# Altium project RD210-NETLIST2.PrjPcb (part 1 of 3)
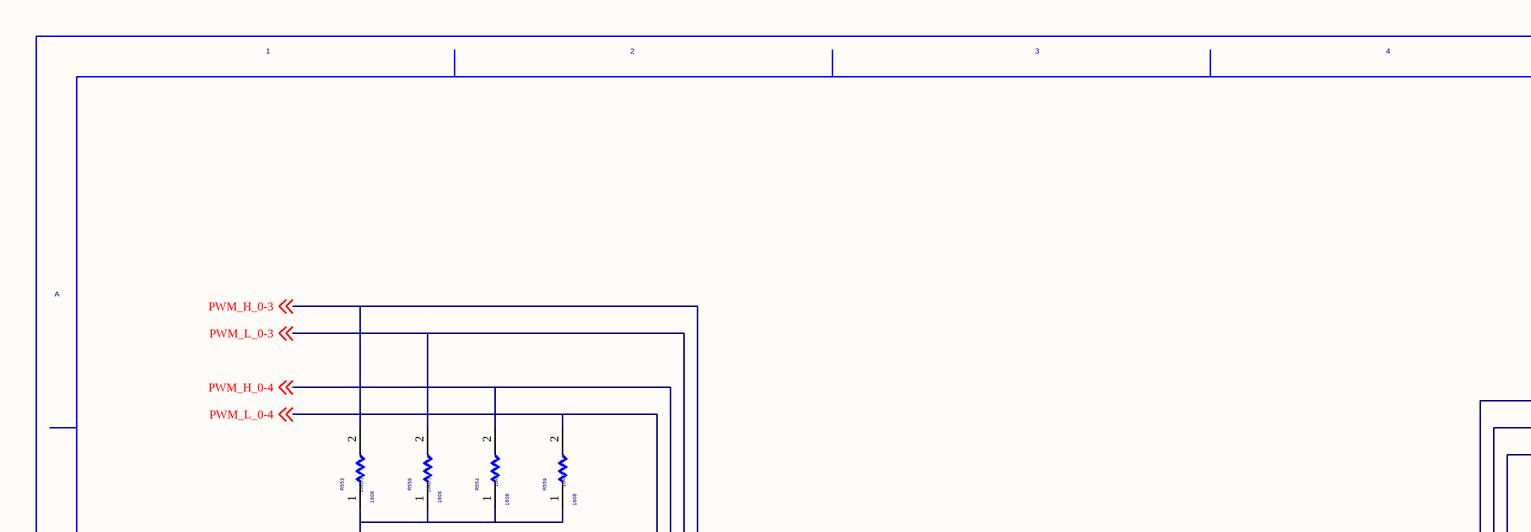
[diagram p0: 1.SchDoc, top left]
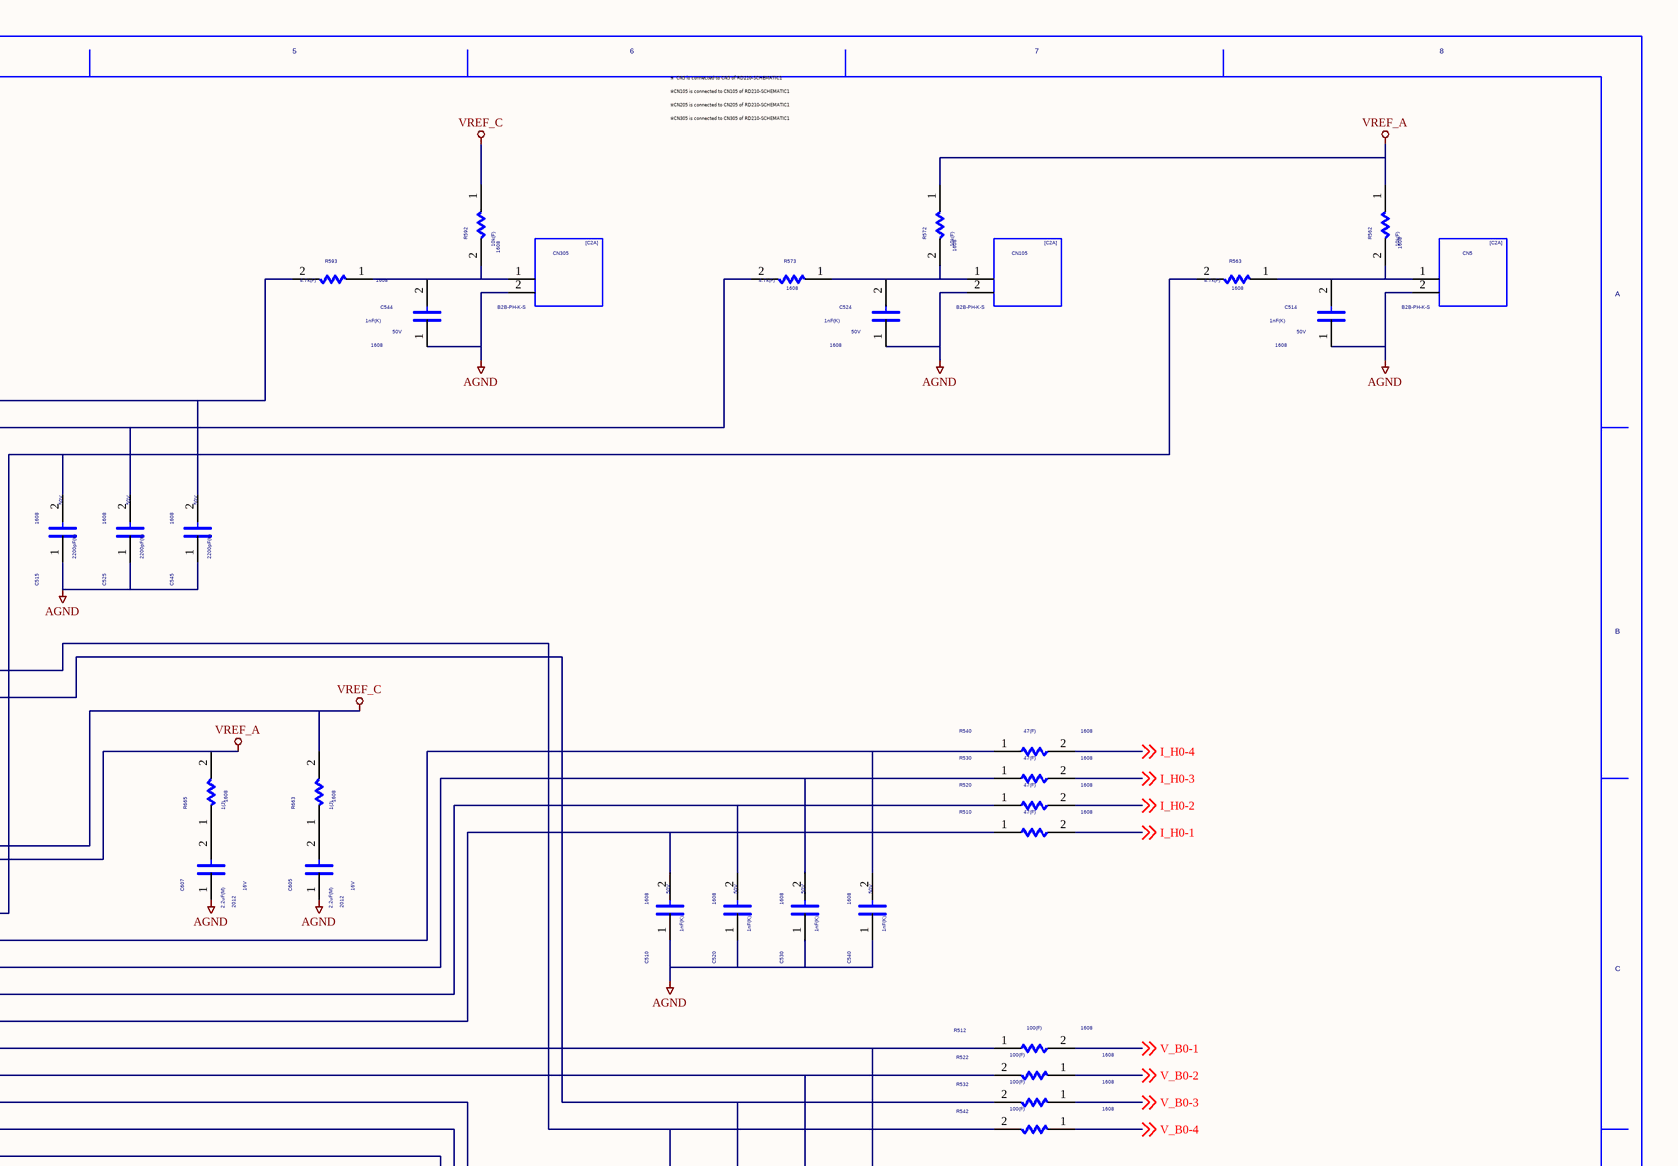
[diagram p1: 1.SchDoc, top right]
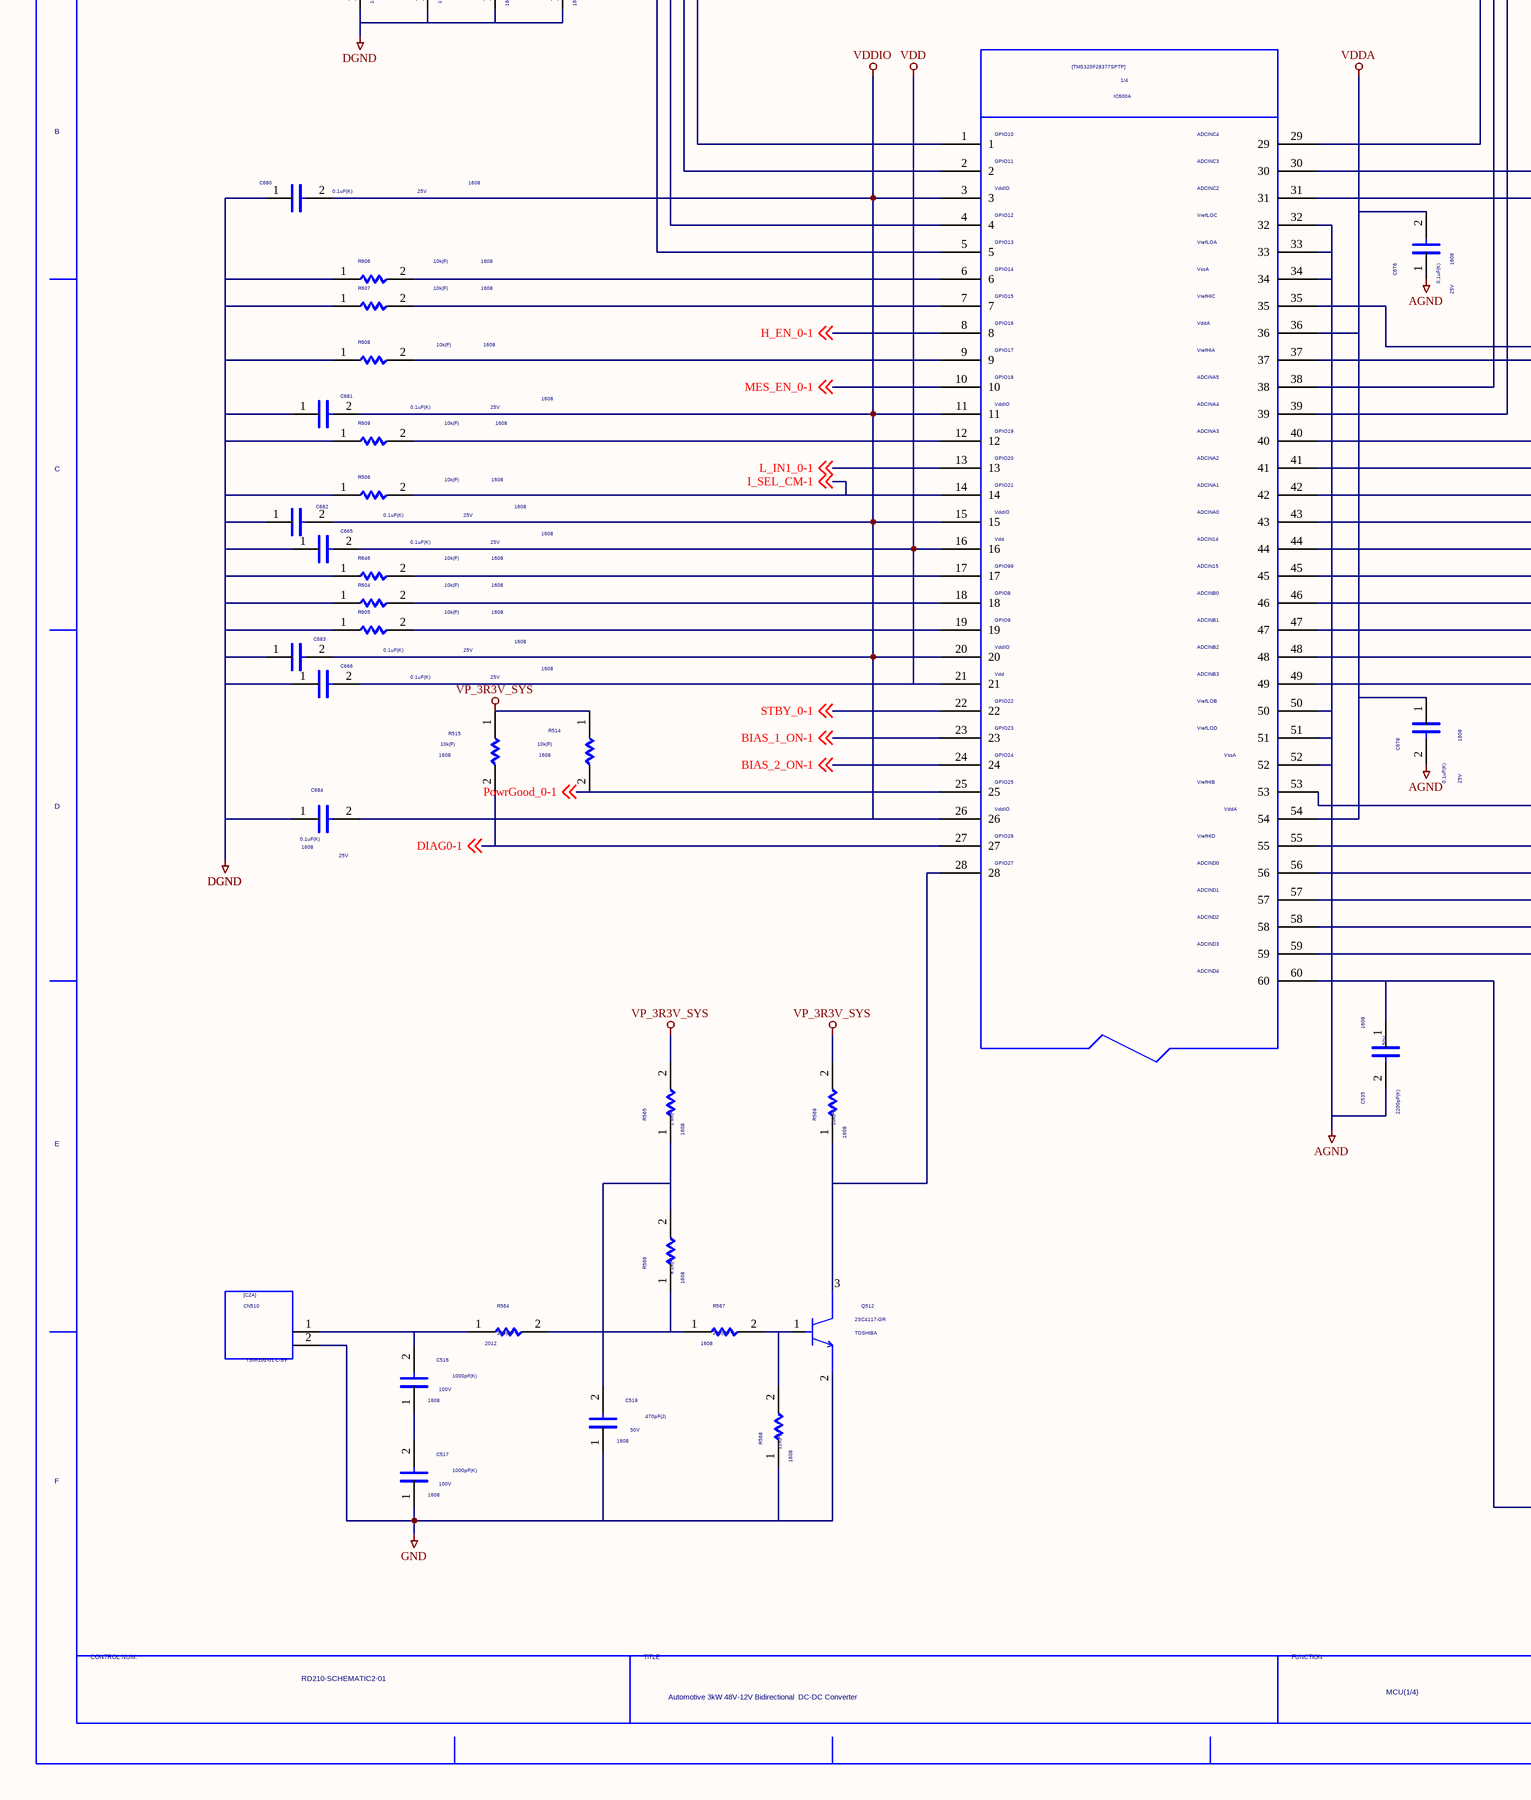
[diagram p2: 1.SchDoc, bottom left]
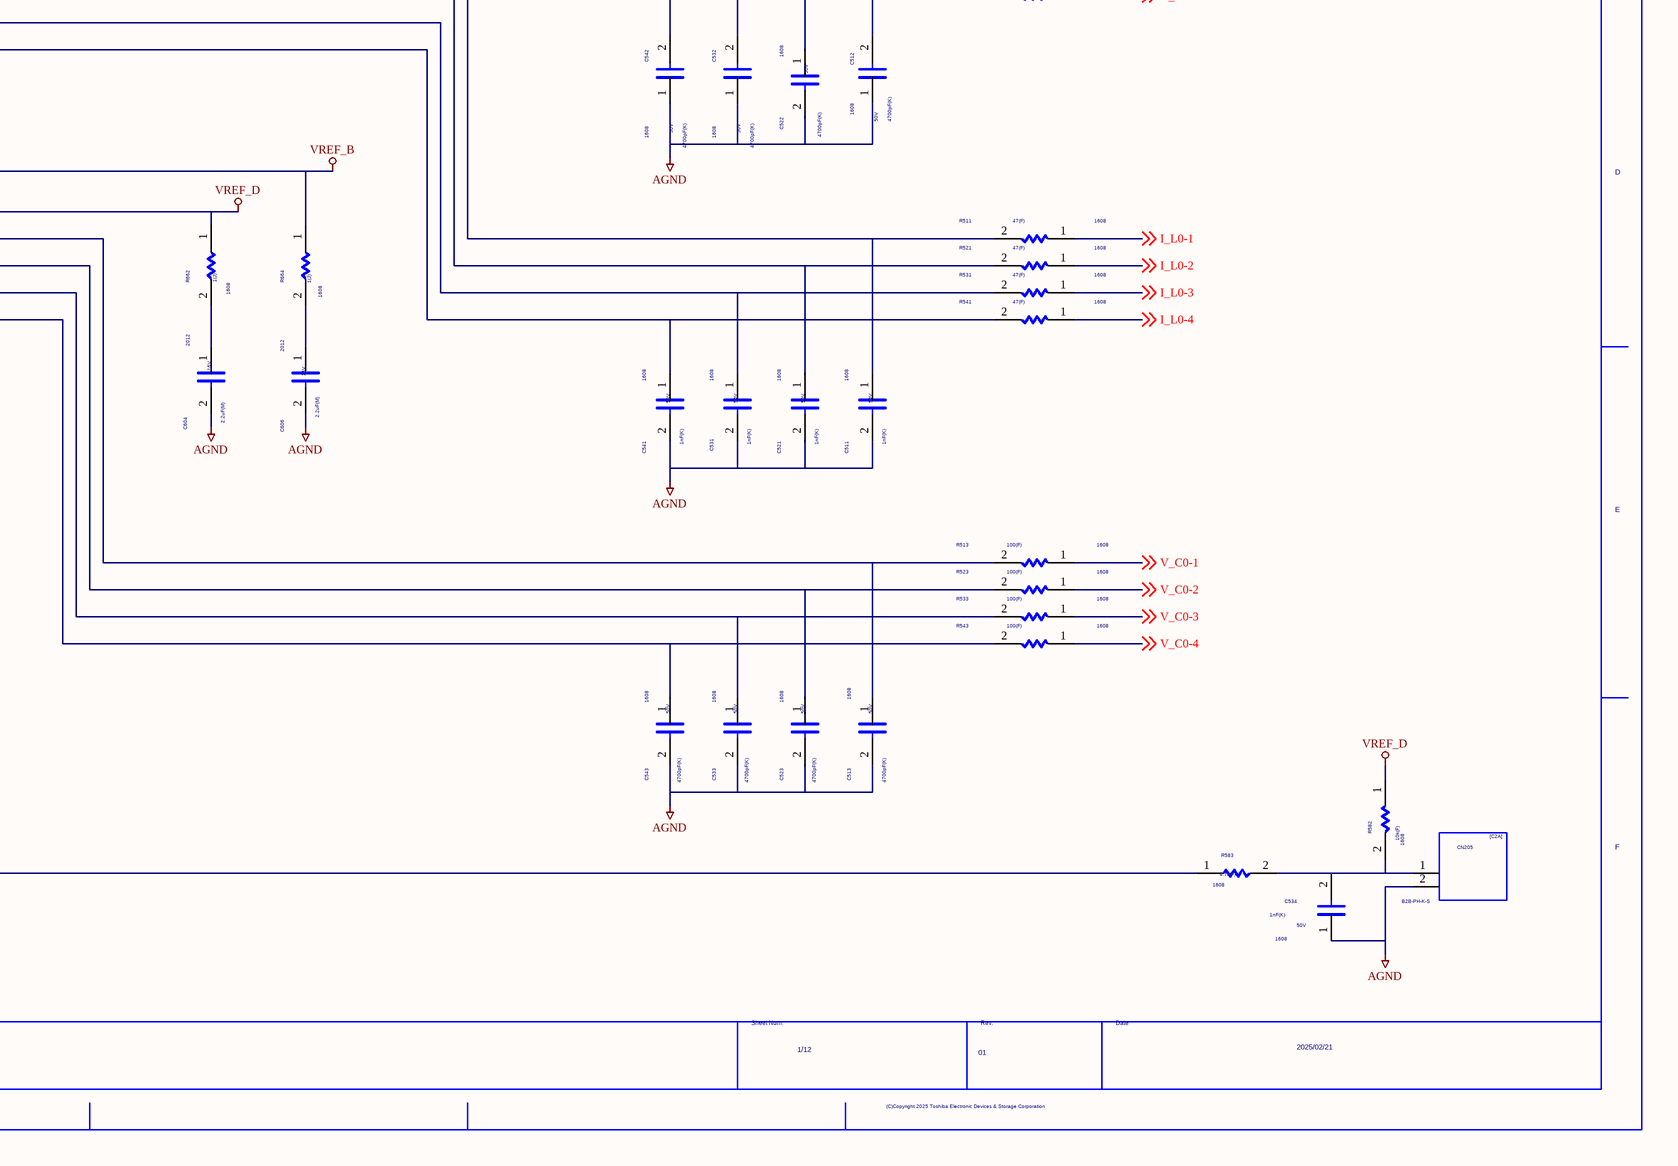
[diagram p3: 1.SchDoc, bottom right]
12 sheets, 1055 parts. Net scope: global (net labels, ports and power ports of the same name join across sheets).
Sheets:
  1.SchDoc
  2.SchDoc
  3.SchDoc
  4.SchDoc
  5.SchDoc
  6.SchDoc
  7.SchDoc
  8.SchDoc
  9.SchDoc
  10.SchDoc
  11.SchDoc
  12.SchDoc

## Sheet 1.SchDoc
size 609 x 444 mm

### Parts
(Parts that share a designator on the sheet are numbered #1, #2 ... from top to bottom, then left to right.)
C510  VAL1: 1nF(K)  VAL2: 50V  SIZECODESMD: 1608  (hidden comment: C)
C511  VAL1: 1nF(K)  VAL2: 50V  SIZECODESMD: 1608  (hidden comment: C)
C512  VAL1: 4700pF(K)  VAL2: 50V  SIZECODESMD: 1608  (hidden comment: C)
C513  VAL1: 4700pF(K)  VAL2: 50V  SIZECODESMD: 1608  (hidden comment: C)
C514  VAL1: 1nF(K)  VAL2: 50V  SIZECODESMD: 1608  (hidden comment: C)
C515  VAL1: 2200pF(K)  VAL2: 50V  SIZECODESMD: 1608  (hidden comment: C)
C516  VAL1: 1000pF(K)  VAL2: 100V  SIZECODESMD: 1608  (hidden comment: C)
C517  VAL1: 1000pF(K)  VAL2: 100V  SIZECODESMD: 1608  (hidden comment: C)
C518  VAL1: 470pF(J)  VAL2: 50V  SIZECODESMD: 1608  (hidden comment: C)
C520  VAL1: 1nF(K)  VAL2: 50V  SIZECODESMD: 1608  (hidden comment: C)
C521  VAL1: 1nF(K)  VAL2: 50V  SIZECODESMD: 1608  (hidden comment: C)
C522  VAL1: 4700pF(K)  VAL2: 50V  SIZECODESMD: 1608  (hidden comment: C)
C523  VAL1: 4700pF(K)  VAL2: 50V  SIZECODESMD: 1608  (hidden comment: C)
C524  VAL1: 1nF(K)  VAL2: 50V  SIZECODESMD: 1608  (hidden comment: C)
C525  VAL1: 2200pF(K)  VAL2: 50V  SIZECODESMD: 1608  (hidden comment: C)
C530  VAL1: 1nF(K)  VAL2: 50V  SIZECODESMD: 1608  (hidden comment: C)
C531  VAL1: 1nF(K)  VAL2: 50V  SIZECODESMD: 1608  (hidden comment: C)
C532  VAL1: 4700pF(K)  VAL2: 50V  SIZECODESMD: 1608  (hidden comment: C)
C533  VAL1: 4700pF(K)  VAL2: 50V  SIZECODESMD: 1608  (hidden comment: C)
C534  VAL1: 1nF(K)  VAL2: 50V  SIZECODESMD: 1608  (hidden comment: C)
C535  VAL1: 2200pF(K)  VAL2: 50V  SIZECODESMD: 1608  (hidden comment: C)
C540  VAL1: 1nF(K)  VAL2: 50V  SIZECODESMD: 1608  (hidden comment: C)
C541  VAL1: 1nF(K)  VAL2: 50V  SIZECODESMD: 1608  (hidden comment: C)
C542  VAL1: 4700pF(K)  VAL2: 50V  SIZECODESMD: 1608  (hidden comment: C)
C543  VAL1: 4700pF(K)  VAL2: 50V  SIZECODESMD: 1608  (hidden comment: C)
C544  VAL1: 1nF(K)  VAL2: 50V  SIZECODESMD: 1608  (hidden comment: C)
C545  VAL1: 2200pF(K)  VAL2: 50V  SIZECODESMD: 1608  (hidden comment: C)
C604  VAL1: 2.2uF(M)  VAL2: 16V  SIZECODESMD: 2012  (hidden comment: C)
C605  VAL1: 2.2uF(M)  VAL2: 16V  SIZECODESMD: 2012  (hidden comment: C)
C606  VAL1: 2.2uF(M)  VAL2: 16V  SIZECODESMD: 2012  (hidden comment: C)
C607  VAL1: 2.2uF(M)  VAL2: 16V  SIZECODESMD: 2012  (hidden comment: C)
C665  VAL1: 0.1uF(K)  VAL2: 25V  SIZECODESMD: 1608  (hidden comment: C)
C666  VAL1: 0.1uF(K)  VAL2: 25V  SIZECODESMD: 1608  (hidden comment: C)
C676  VAL1: 0.1uF(K)  VAL2: 25V  SIZECODESMD: 1608  (hidden comment: C)
C678  VAL1: 0.1uF(K)  VAL2: 25V  SIZECODESMD: 1608  (hidden comment: C)
C680  VAL1: 0.1uF(K)  VAL2: 25V  SIZECODESMD: 1608  (hidden comment: C)
C681  VAL1: 0.1uF(K)  VAL2: 25V  SIZECODESMD: 1608  (hidden comment: C)
C682  VAL1: 0.1uF(K)  VAL2: 25V  SIZECODESMD: 1608  (hidden comment: C)
C683  VAL1: 0.1uF(K)  VAL2: 25V  SIZECODESMD: 1608  (hidden comment: C)
C684  VAL1: 0.1uF(K)  VAL2: 25V  SIZECODESMD: 1608  (hidden comment: C)
CN5  VAL3: B2B-PH-K-S  (hidden comment: C2A)
CN105  VAL3: B2B-PH-K-S  (hidden comment: C2A)
CN205  VAL3: B2B-PH-K-S  (hidden comment: C2A)
CN305  VAL3: B2B-PH-K-S  (hidden comment: C2A)
CN510  VAL3: TSM-102-01-L-SV  (hidden comment: C2A)
IC600  TMS320F28377SPTP_1  (value not drawn)  (part A of 4)
Q512  USERCOMPTEXT3: TOSHIBA  VAL3: 2SC4117-GR  (hidden comment: TRN)
R506  VAL1: 10k(F)  SIZECODESMD: 1608  (hidden comment: R)
R510  VAL1: 47(F)  SIZECODESMD: 1608  (hidden comment: R)
R511  VAL1: 47(F)  SIZECODESMD: 1608  (hidden comment: R)
R512  VAL1: 100(F)  SIZECODESMD: 1608  (hidden comment: R)
R513  VAL1: 100(F)  SIZECODESMD: 1608  (hidden comment: R)
R514  VAL1: 10k(F)  SIZECODESMD: 1608  (hidden comment: R)
R515  VAL1: 10k(F)  SIZECODESMD: 1608  (hidden comment: R)
R520  VAL1: 47(F)  SIZECODESMD: 1608  (hidden comment: R)
R521  VAL1: 47(F)  SIZECODESMD: 1608  (hidden comment: R)
R522  VAL1: 100(F)  SIZECODESMD: 1608  (hidden comment: R)
R523  VAL1: 100(F)  SIZECODESMD: 1608  (hidden comment: R)
R530  VAL1: 47(F)  SIZECODESMD: 1608  (hidden comment: R)
R531  VAL1: 47(F)  SIZECODESMD: 1608  (hidden comment: R)
R532  VAL1: 100(F)  SIZECODESMD: 1608  (hidden comment: R)
R533  VAL1: 100(F)  SIZECODESMD: 1608  (hidden comment: R)
R540  VAL1: 47(F)  SIZECODESMD: 1608  (hidden comment: R)
R541  VAL1: 47(F)  SIZECODESMD: 1608  (hidden comment: R)
R542  VAL1: 100(F)  SIZECODESMD: 1608  (hidden comment: R)
R543  VAL1: 100(F)  SIZECODESMD: 1608  (hidden comment: R)
R553  VAL1: 10k(F)  SIZECODESMD: 1608  (hidden comment: R)
R554  VAL1: 10k(F)  SIZECODESMD: 1608  (hidden comment: R)
R558  VAL1: 10k(F)  SIZECODESMD: 1608  (hidden comment: R)
R559  VAL1: 10k(F)  SIZECODESMD: 1608  (hidden comment: R)
R562  VAL1: 10k(F)  SIZECODESMD: 1608  (hidden comment: R)
R563  VAL1: 4.7k(F)  SIZECODESMD: 1608  (hidden comment: R)
R564  VAL1: 100(J)  SIZECODESMD: 2012  (hidden comment: R)
R565  VAL1: 1.8k(F)  SIZECODESMD: 1608  (hidden comment: R)
R566  VAL1: 8.2k(F)  SIZECODESMD: 1608  (hidden comment: R)
R567  VAL1: 22k(F)  SIZECODESMD: 1608  (hidden comment: R)
R568  VAL1: 22k(F)  SIZECODESMD: 1608  (hidden comment: R)
R569  VAL1: 10k(F)  SIZECODESMD: 1608  (hidden comment: R)
R572  VAL1: 10k(F)  SIZECODESMD: 1608  (hidden comment: R)
R573  VAL1: 4.7k(F)  SIZECODESMD: 1608  (hidden comment: R)
R582  VAL1: 10k(F)  SIZECODESMD: 1608  (hidden comment: R)
R583  VAL1: 4.7k(F)  SIZECODESMD: 1608  (hidden comment: R)
R592  VAL1: 10k(F)  SIZECODESMD: 1608  (hidden comment: R)
R593  VAL1: 4.7k(F)  SIZECODESMD: 1608  (hidden comment: R)
R604  VAL1: 10k(F)  SIZECODESMD: 1608  (hidden comment: R)
R605  VAL1: 10k(F)  SIZECODESMD: 1608  (hidden comment: R)
R606  VAL1: 10k(F)  SIZECODESMD: 1608  (hidden comment: R)
R607  VAL1: 10k(F)  SIZECODESMD: 1608  (hidden comment: R)
R608  VAL1: 10k(F)  SIZECODESMD: 1608  (hidden comment: R)
R609  VAL1: 10k(F)  SIZECODESMD: 1608  (hidden comment: R)
R646  VAL1: 10k(F)  SIZECODESMD: 1608  (hidden comment: R)
R662  VAL1: 1(J)  SIZECODESMD: 1608  (hidden comment: R)
R663  VAL1: 1(J)  SIZECODESMD: 1608  (hidden comment: R)
R664  VAL1: 1(J)  SIZECODESMD: 1608  (hidden comment: R)
R665  VAL1: 1(J)  SIZECODESMD: 1608  (hidden comment: R)
U?#1  DATE: 2025/02/21  DRAWINGNUMBER: RD210-SCHEMATIC2-01  TITLE: Automotive 3kW 48V-12V Bidirectional / DC-DC Converter  FUNCTION: MCU(1/4)  SHEETNUMBER: 1/12  REVISION: 01  (hidden comment: WAKU_DEF_A3)

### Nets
AGND: C510.1 C511.2 C512.1 C513.2 C514.1 C515.1 C520.1 C521.2 C522.2 C523.2 C524.1 C525.1 C530.1 C531.2 C532.1 C533.2 C534.1 C535.2 C540.1 C541.2 C542.1 C543.2 C544.1 C545.1 C604.2 C605.1 C606.2 C607.1 C676.1 C678.2 CN5.2 CN105.2 CN205.2 CN305.2 IC600.32 IC600.33 IC600.34 IC600.50 IC600.51 IC600.52
DGND: C665.1 C666.1 C680.1 C681.1 C682.1 C683.1 C684.1 R506.1 R553.1 R554.1 R558.1 R559.1 R604.1 R605.1 R606.1 R607.1 R608.1 R609.1 R646.1
GND: C517.1 C518.1 CN510.2 Q512.2(E) R568.1
VDD: C665.2 C666.2 IC600.16 IC600.21
VDDA: C676.2 C678.1 IC600.36 IC600.54
VDDIO: C680.2 C681.2 C682.2 C683.2 C684.2 IC600.3 IC600.11 IC600.15 IC600.20 IC600.26
VP_3R3V_SYS: R514.1 R515.1 R565.2 R569.2
VREF_A: IC600.37 R562.1 R572.1 R665.2
VREF_B: IC600.53 R664.1
VREF_C: IC600.35 R592.1 R663.2
VREF_D: IC600.55 R582.1 R662.1
BIAS_1_ON-1: IC600.23 ; off-sheet BIAS_1_ON-1
BIAS_2_ON-1: IC600.24 ; off-sheet BIAS_2_ON-1
DIAG0-1: IC600.27 R515.2 ; off-sheet DIAG0-1
H_EN_0-1: IC600.8 ; off-sheet H_EN_0-1
I_H0-1: R510.2 ; off-sheet I_H0-1
I_H0-2: R520.2 ; off-sheet I_H0-2
I_H0-3: R530.2 ; off-sheet I_H0-3
I_H0-4: R540.2 ; off-sheet I_H0-4
I_L0-1: R511.1 ; off-sheet I_L0-1
I_L0-2: R521.1 ; off-sheet I_L0-2
I_L0-3: R531.1 ; off-sheet I_L0-3
I_L0-4: R541.1 ; off-sheet I_L0-4
I_SEL_CM-1: IC600.14 R506.2 ; off-sheet I_SEL_CM-1
L_IN1_0-1: IC600.13 ; off-sheet L_IN1_0-1
MES_EN_0-1: IC600.10 ; off-sheet MES_EN_0-1
PowrGood_0-1: IC600.25 R514.2 ; off-sheet PowrGood_0-1
PWM_H_0-3: IC600.1 R553.2 ; off-sheet PWM_H_0-3
PWM_H_0-4: IC600.4 R554.2 ; off-sheet PWM_H_0-4
PWM_L_0-3: IC600.2 R558.2 ; off-sheet PWM_L_0-3
PWM_L_0-4: IC600.5 R559.2 ; off-sheet PWM_L_0-4
SIG569: IC600.9 R608.2
SIG570: IC600.6 R606.2
SIG571: IC600.7 R607.2
SIG572: IC600.12 R609.2
SIG573: IC600.17 R646.2
SIG574: IC600.18 R604.2
SIG575: IC600.19 R605.2
SIG592: C532.2 IC600.31 R532.2
SIG593: C525.2 IC600.38 R573.2
SIG595: C512.2 IC600.44 R512.1
SIG597: C520.2 IC600.42 R520.1
SIG598: C530.2 IC600.41 R530.1
SIG599: C540.2 IC600.40 R540.1
SIG606: C542.2 IC600.30 R542.2
SIG608: C545.2 IC600.29 R593.2
SIG611: C544.2 CN305.1 R592.2 R593.1
SIG613: C524.2 CN105.1 R572.2 R573.1
SIG616: C514.2 CN5.1 R562.2 R563.1
SIG623: C510.2 IC600.43 R510.1
SIG626: C531.1 IC600.48 R531.2
SIG627: C541.1 IC600.49 R541.2
SIG628: C521.1 IC600.47 R521.2
SIG629: C511.1 IC600.46 R511.2
SIG630: C522.1 IC600.45 R522.2
SIG634: C515.2 IC600.39 R563.2
SIG635: C606.1 R664.2
SIG636: C604.1 R662.2
SIG638: C535.1 IC600.60 R583.1
SIG639: C543.1 IC600.59 R543.2
SIG640: C533.1 IC600.58 R533.2
SIG641: C523.1 IC600.57 R523.2
SIG642: C513.1 IC600.56 R513.2
SIG694: IC600.28 Q512.3(C) R569.1
SIG697: Q512.1(B) R567.2 R568.2
SIG698: R564.2 R566.1 R567.1
SIG700: C518.2 R565.1 R566.2
SIG701: C516.1 C517.2
SIG702: C516.2 CN510.1 R564.1
STBY_0-1: IC600.22 ; off-sheet STBY_0-1
TH-2: C534.2 CN205.1 R582.2 R583.2
V_B0-1: R512.2 ; off-sheet V_B0-1
V_B0-2: R522.1 ; off-sheet V_B0-2
V_B0-3: R532.1 ; off-sheet V_B0-3
V_B0-4: R542.1 ; off-sheet V_B0-4
V_C0-1: R513.1 ; off-sheet V_C0-1
V_C0-2: R523.1 ; off-sheet V_C0-2
V_C0-3: R533.1 ; off-sheet V_C0-3
V_C0-4: R543.1 ; off-sheet V_C0-4
NetC605_2: C605.2 R663.1
NetC607_2: C607.2 R665.1

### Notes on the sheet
- ※CN305 is connected to CN305 of RD210-SCHEMATIC1
- ※CN105 is connected to CN105 of RD210-SCHEMATIC1
- ※  CN5 is connected to CN5 of RD210-SCHEMATIC1
- ※CN205 is connected to CN205 of RD210-SCHEMATIC1

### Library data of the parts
C510-C518 C520-C525 C530-C535 C540-C545 C604-C607 C665 C666 C676 C678 C680-C684 = C: OriginalSymbolOrigin: (2540,7620)
CN5 CN105 CN205 CN305 CN510 = C2A: SAVEAREA0: -4611,-206,24632,18258; SAVECOUNT: 25; TIME: 13:28:28; UPDATEUSER: tomizawa-y; UPDATETIME: 12:08:31; OriginalSymbolOrigin: (2540,15240); CDBNAME: CN
IC600 = TMS320F28377SPTP_1: TIME: 14:21:47; UPDATEUSER: sptcae13; UPDATETIME: 11:28:17; SAVECOUNT: 36; SAVEAREA0: -164425,-192040,236003,1269; OriginalSymbolOrigin: (7620,0); CaptureCellPackProp: TMS320F28377SPTP_1A; USERCOMPTEXT3: TOSHIBA; CDBNAME: IC
Q512 = TRN: TIME: 09:39:04; UPDATEUSER: 19910145; UPDATETIME: 15:12:10; SAVECOUNT: 8; SAVEAREA0: -6194,-158,18648,15662; OriginalSymbolOrigin: (2540,17780); CDBNAME: Q
R506 R510-R515 R520-R523 R530-R533 R540-R543 R553 R554 R558 R559 R562 R563 R569 R572 R573 R582 R583 R592 R593 R604-R609 R646 = R: VAL2: 200mW; OriginalSymbolOrigin: (5080,5080)
R564 = R: VAL2: 250mW; OriginalSymbolOrigin: (5080,5080)
R565-R568 = R: VAL2: 333mW; OriginalSymbolOrigin: (5080,5080)
R662-R665 = R: VAL2: 125mW; OriginalSymbolOrigin: (5080,5080)
U?#1 = WAKU_DEF_A3: PLOTTIME: HH:MM; SAVEAREA0: 185750,-43960,448537,75779; TIME: 14:30:25; UPDATEUSER: t5459927; UPDATETIME: 06:59:19; SAVECOUNT: 19; ZONEOFFSETX: 36; ZONEOFFSETY: -24; OriginalSymbolOrigin: (12700,-12700); SHTSAVECOUNT: 205

## Sheet 2.SchDoc
size 609 x 444 mm
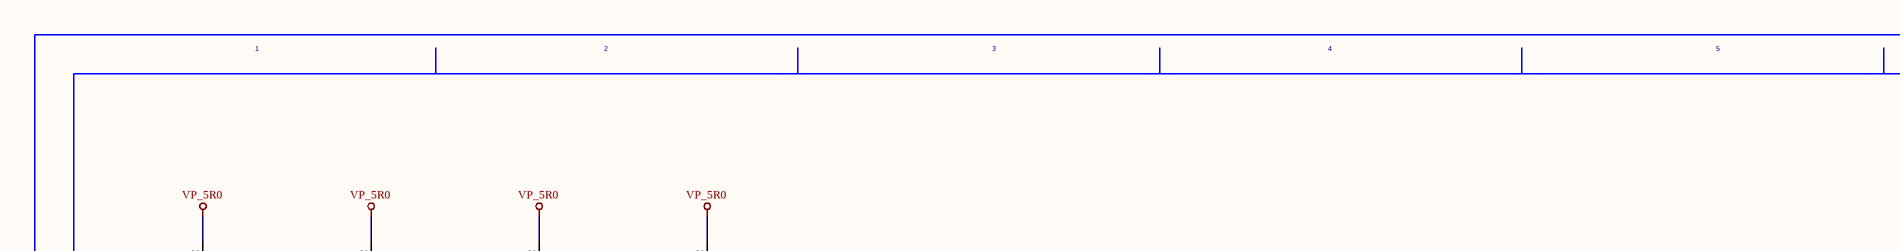
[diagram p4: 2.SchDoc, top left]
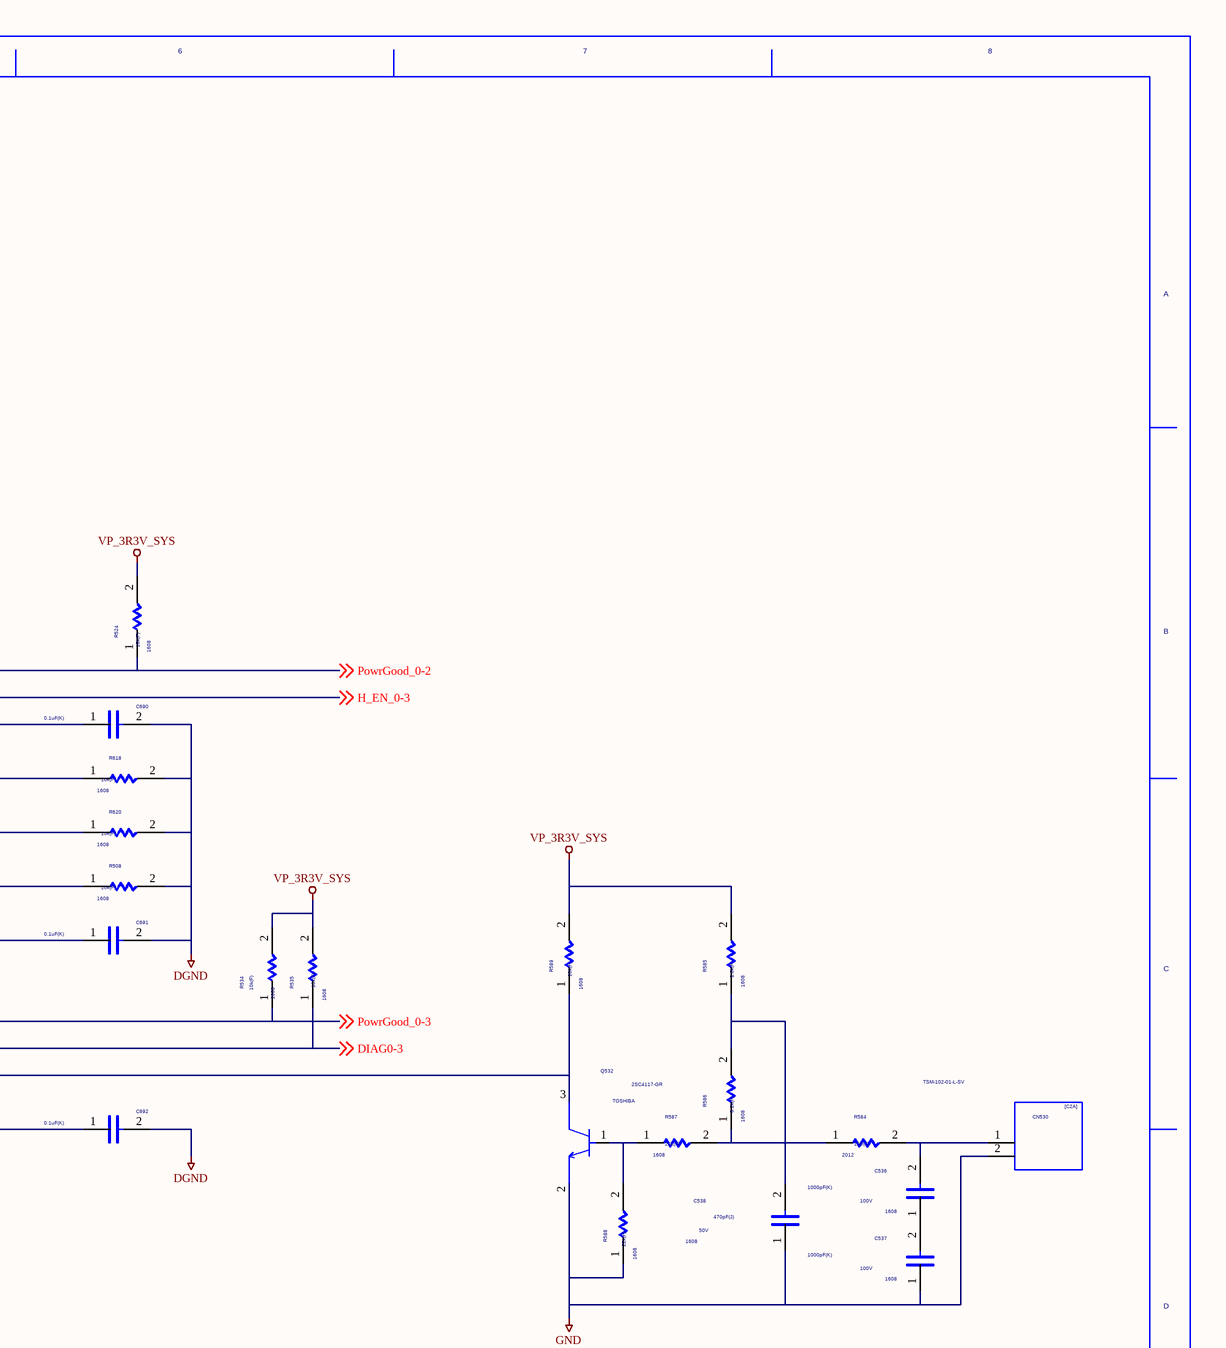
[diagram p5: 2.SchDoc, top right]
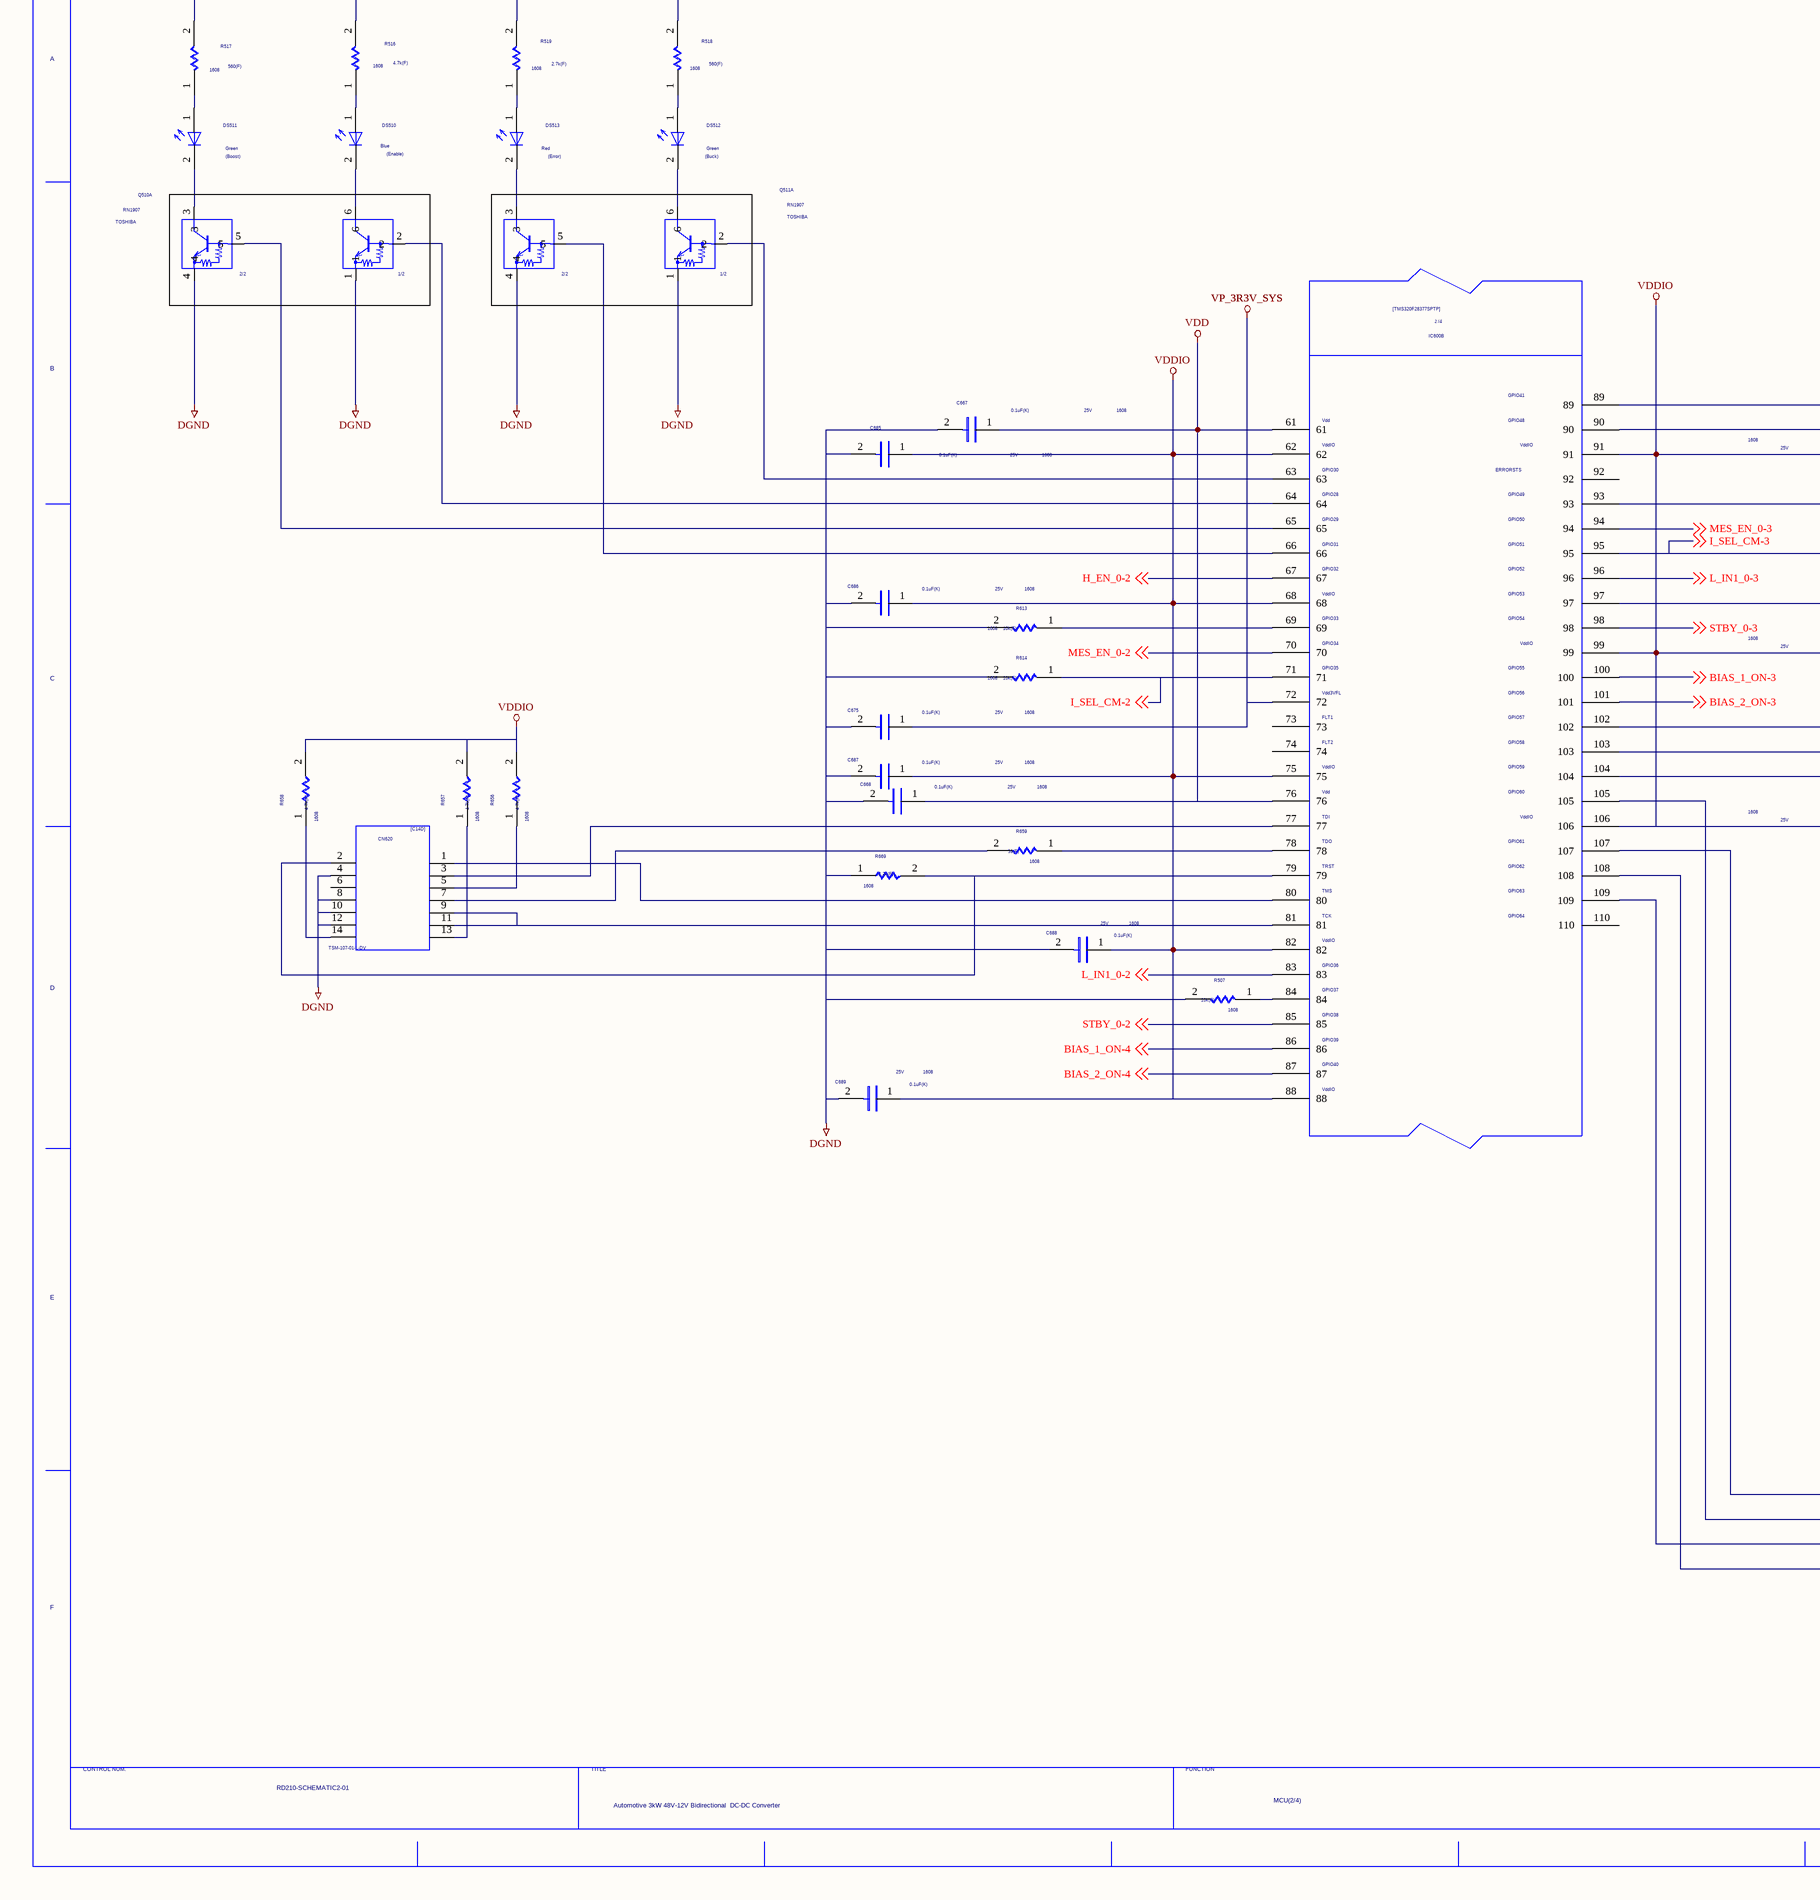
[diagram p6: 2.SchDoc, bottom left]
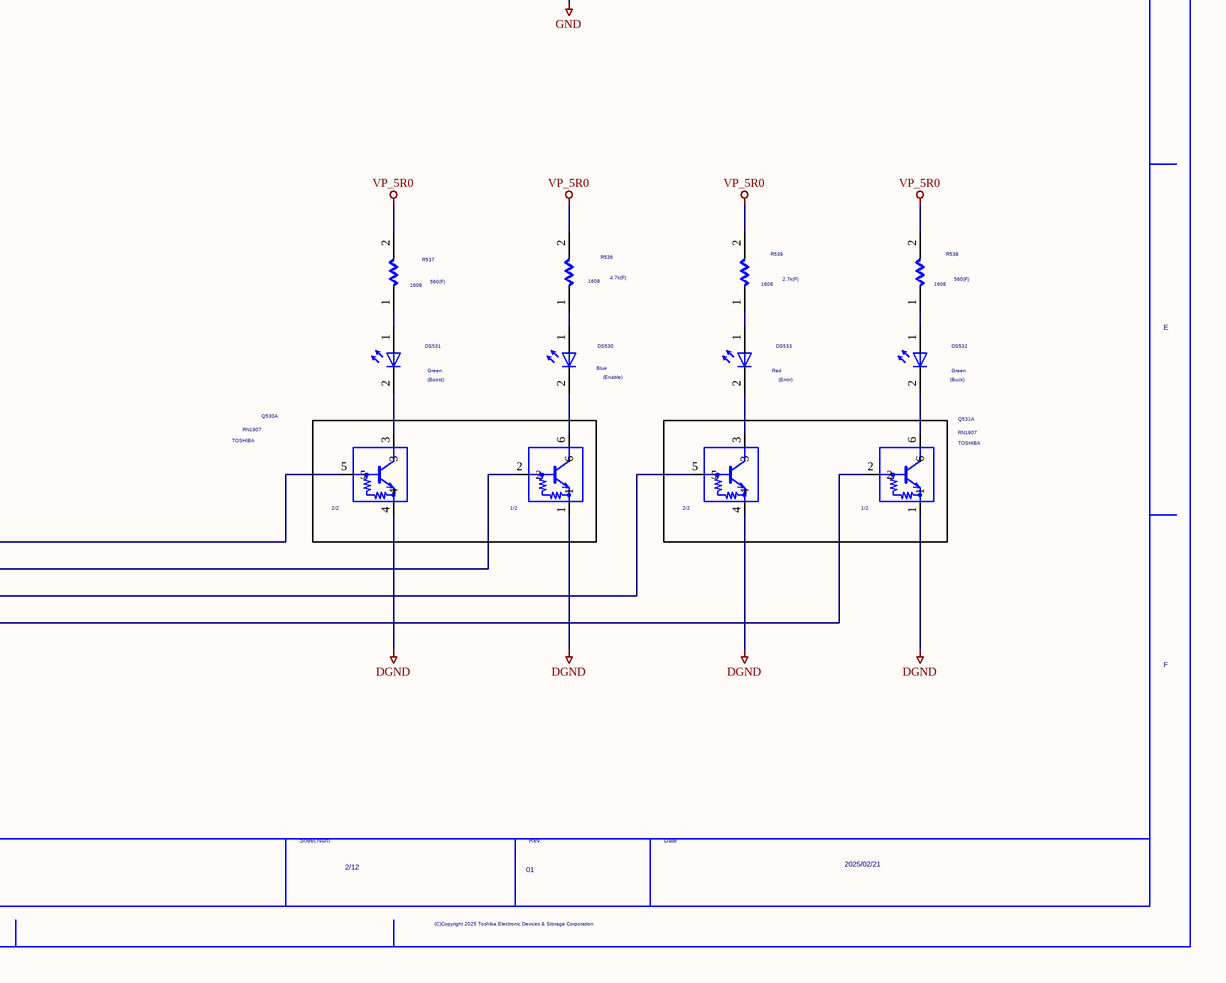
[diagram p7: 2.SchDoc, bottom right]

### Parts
(Parts that share a designator on the sheet are numbered #1, #2 ... from top to bottom, then left to right.)
C536  VAL1: 1000pF(K)  VAL2: 100V  SIZECODESMD: 1608  (hidden comment: C)
C537  VAL1: 1000pF(K)  VAL2: 100V  SIZECODESMD: 1608  (hidden comment: C)
C538  VAL1: 470pF(J)  VAL2: 50V  SIZECODESMD: 1608  (hidden comment: C)
C667  VAL1: 0.1uF(K)  VAL2: 25V  SIZECODESMD: 1608  (hidden comment: C)
C668  VAL1: 0.1uF(K)  VAL2: 25V  SIZECODESMD: 1608  (hidden comment: C)
C675  VAL1: 0.1uF(K)  VAL2: 25V  SIZECODESMD: 1608  (hidden comment: C)
C685  VAL1: 0.1uF(K)  VAL2: 25V  SIZECODESMD: 1608  (hidden comment: C)
C686  VAL1: 0.1uF(K)  VAL2: 25V  SIZECODESMD: 1608  (hidden comment: C)
C687  VAL1: 0.1uF(K)  VAL2: 25V  SIZECODESMD: 1608  (hidden comment: C)
C688  VAL1: 0.1uF(K)  VAL2: 25V  SIZECODESMD: 1608  (hidden comment: C)
C689  VAL1: 0.1uF(K)  VAL2: 25V  SIZECODESMD: 1608  (hidden comment: C)
C690  VAL1: 0.1uF(K)  VAL2: 25V  SIZECODESMD: 1608  (hidden comment: C)
C691  VAL1: 0.1uF(K)  VAL2: 25V  SIZECODESMD: 1608  (hidden comment: C)
C692  VAL1: 0.1uF(K)  VAL2: 25V  SIZECODESMD: 1608  (hidden comment: C)
CN530  VAL3: TSM-102-01-L-SV  (hidden comment: C2A)
CN620  VAL3: TSM-107-01-L-DV  (hidden comment: C14D)
DS510  VAL1: Blue  USERCOMPTEXT1: (Enable)  (hidden comment: LED)
DS511  VAL1: Green  USERCOMPTEXT1: (Boost)  (hidden comment: LED)
DS512  VAL1: Green  USERCOMPTEXT1: (Buck)  (hidden comment: LED)
DS513  VAL1: Red  USERCOMPTEXT1: (Error)  (hidden comment: LED)
DS530  VAL1: Blue  USERCOMPTEXT1: (Enable)  (hidden comment: LED)
DS531  VAL1: Green  USERCOMPTEXT1: (Boost)  (hidden comment: LED)
DS532  VAL1: Green  USERCOMPTEXT1: (Buck)  (hidden comment: LED)
DS533  VAL1: Red  USERCOMPTEXT1: (Error)  (hidden comment: LED)
IC600  TMS320F28377SPTP_1  (value not drawn)  (part B of 4)
Q510  USERCOMPTEXT1: 1/2  USERCOMPTEXT3: TOSHIBA  VAL3: RN1907  (hidden comment: RN1907_Q1)  (parts A,B of 2)
Q511  USERCOMPTEXT1: 1/2  USERCOMPTEXT3: TOSHIBA  VAL3: RN1907  (hidden comment: RN1907_Q1)  (parts A,B of 2)
Q530  USERCOMPTEXT1: 1/2  USERCOMPTEXT3: TOSHIBA  VAL3: RN1907  (hidden comment: RN1907_Q1)  (parts A,B of 2)
Q531  USERCOMPTEXT1: 1/2  USERCOMPTEXT3: TOSHIBA  VAL3: RN1907  (hidden comment: RN1907_Q1)  (parts A,B of 2)
Q532  USERCOMPTEXT3: TOSHIBA  VAL3: 2SC4117-GR  (hidden comment: TRN)
R507  VAL1: 10k(F)  SIZECODESMD: 1608  (hidden comment: R)
R508  VAL1: 10k(F)  SIZECODESMD: 1608  (hidden comment: R)
R516  VAL1: 4.7k(F)  SIZECODESMD: 1608  (hidden comment: R)
R517  VAL1: 560(F)  SIZECODESMD: 1608  (hidden comment: R)
R518  VAL1: 560(F)  SIZECODESMD: 1608  (hidden comment: R)
R519  VAL1: 2.7k(F)  SIZECODESMD: 1608  (hidden comment: R)
R524  VAL1: 10k(F)  SIZECODESMD: 1608  (hidden comment: R)
R534  VAL1: 10k(F)  SIZECODESMD: 1608  (hidden comment: R)
R535  VAL1: 10k(F)  SIZECODESMD: 1608  (hidden comment: R)
R536  VAL1: 4.7k(F)  SIZECODESMD: 1608  (hidden comment: R)
R537  VAL1: 560(F)  SIZECODESMD: 1608  (hidden comment: R)
R538  VAL1: 560(F)  SIZECODESMD: 1608  (hidden comment: R)
R539  VAL1: 2.7k(F)  SIZECODESMD: 1608  (hidden comment: R)
R584  VAL1: 100(J)  SIZECODESMD: 2012  (hidden comment: R)
R585  VAL1: 1.8k(F)  SIZECODESMD: 1608  (hidden comment: R)
R586  VAL1: 8.2k(F)  SIZECODESMD: 1608  (hidden comment: R)
R587  VAL1: 22k(F)  SIZECODESMD: 1608  (hidden comment: R)
R588  VAL1: 22k(F)  SIZECODESMD: 1608  (hidden comment: R)
R589  VAL1: 10k(F)  SIZECODESMD: 1608  (hidden comment: R)
R613  VAL1: 10k(F)  SIZECODESMD: 1608  (hidden comment: R)
R614  VAL1: 10k(F)  SIZECODESMD: 1608  (hidden comment: R)
R618  VAL1: 10k(F)  SIZECODESMD: 1608  (hidden comment: R)
R620  VAL1: 10k(F)  SIZECODESMD: 1608  (hidden comment: R)
R656  VAL1: 4.7k(F)  SIZECODESMD: 1608  (hidden comment: R)
R657  VAL1: 4.7k(F)  SIZECODESMD: 1608  (hidden comment: R)
R658  VAL1: 4.7k(F)  SIZECODESMD: 1608  (hidden comment: R)
R659  VAL1: 39(F)  SIZECODESMD: 1608  (hidden comment: R)
R669  VAL1: 2.2k(F)  SIZECODESMD: 1608  (hidden comment: R)
U?#2  DATE: 2025/02/21  DRAWINGNUMBER: RD210-SCHEMATIC2-01  TITLE: Automotive 3kW 48V-12V Bidirectional / DC-DC Converter  FUNCTION: MCU(2/4)  SHEETNUMBER: 2/12  REVISION: 01  (hidden comment: WAKU_DEF_A3)

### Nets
DGND: C667.2 C668.2 C675.2 C685.2 C686.2 C687.2 C688.2 C689.2 C690.2 C691.2 C692.2 CN620.4 CN620.8 CN620.10 CN620.12 Q510.1 Q510.4 Q511.1 Q511.4 Q530.1 Q530.4 Q531.1 Q531.4 R507.2 R508.2 R613.2 R614.2 R618.2 R620.2 R669.1
GND: C537.1 C538.1 CN530.2 Q532.2(E) R588.1
VDD: C667.1 C668.1 IC600.61 IC600.76
VDDIO: C685.1 C686.1 C687.1 C688.1 C689.1 C690.1 C691.1 C692.1 IC600.62 IC600.68 IC600.75 IC600.82 IC600.88 IC600.91 IC600.99 IC600.106 R656.2 R657.2 R658.2
VP_3R3V_SYS: C675.1 IC600.72 R524.2 R534.2 R535.2 R585.2 R589.2
VP_5R0: R516.2 R517.2 R518.2 R519.2 R536.2 R537.2 R538.2 R539.2
BIAS_1_ON-3: IC600.100 ; off-sheet BIAS_1_ON-3
BIAS_1_ON-4: IC600.86 ; off-sheet BIAS_1_ON-4
BIAS_2_ON-3: IC600.101 ; off-sheet BIAS_2_ON-3
BIAS_2_ON-4: IC600.87 ; off-sheet BIAS_2_ON-4
DIAG0-3: IC600.103 R535.1 ; off-sheet DIAG0-3
H_EN_0-2: IC600.67 ; off-sheet H_EN_0-2
H_EN_0-3: IC600.90 ; off-sheet H_EN_0-3
H_EN_0-4: IC600.110
I_SEL_CM-2: IC600.71 R614.1 ; off-sheet I_SEL_CM-2
I_SEL_CM-3: IC600.95 R620.1 ; off-sheet I_SEL_CM-3
L_IN1_0-2: IC600.83 ; off-sheet L_IN1_0-2
L_IN1_0-3: IC600.96 ; off-sheet L_IN1_0-3
MES_EN_0-2: IC600.70 ; off-sheet MES_EN_0-2
MES_EN_0-3: IC600.94 ; off-sheet MES_EN_0-3
PowrGood_0-2: IC600.89 R524.1 ; off-sheet PowrGood_0-2
PowrGood_0-3: IC600.102 R534.1 ; off-sheet PowrGood_0-3
SIG0026: DS531.2(C) Q530.3
SIG0027: DS530.2(C) Q530.6
SIG0028: DS533.2(C) Q531.3
SIG0029: DS532.2(C) Q531.6
SIG00215: DS511.1(A) R517.1
SIG00216: DS512.1(A) R518.1
SIG00217: DS510.1(A) R516.1
SIG00218: DS512.2(C) Q511.6
SIG00219: DS510.2(C) Q510.6
SIG00220: DS513.2(C) Q511.3
SIG00223: DS511.2(C) Q510.3
SIG00226: DS513.1(A) R519.1
SIG00236: IC600.65 Q510.5
SIG00237: IC600.64 Q510.2
SIG00238: IC600.66 Q511.5
SIG00239: IC600.63 Q511.2
SIG665: IC600.69 R613.1
SIG669: IC600.78 R659.1
SIG671: IC600.84 R507.1
SIG674: CN620.2 IC600.79 R669.2
SIG675: CN620.3 IC600.77
SIG676: CN620.7 R659.2
SIG677: CN620.1 IC600.80
SIG678: CN620.9 CN620.11 IC600.81
SIG680: CN620.14 R658.1
SIG681: CN620.13 R657.1
SIG682: CN620.5 R656.1
SIG686: IC600.93 R618.1
SIG689: IC600.97 R508.1
SIG705: R584.1 R586.1 R587.2
SIG706: C536.2 CN530.1 R584.2
SIG709: Q532.1(B) R587.1 R588.2
SIG710: IC600.104 Q532.3(C) R589.1
SIG713: DS530.1(A) R536.1
SIG715: DS533.1(A) R539.1
SIG717: DS531.1(A) R537.1
SIG719: DS532.1(A) R538.1
SIG724: IC600.105 Q530.2
SIG725: IC600.107 Q530.5
SIG726: IC600.108 Q531.2
SIG727: IC600.109 Q531.5
SIG729: C538.2 R585.1 R586.2
STBY_0-2: IC600.85 ; off-sheet STBY_0-2
STBY_0-3: IC600.98 ; off-sheet STBY_0-3
NetC536_1: C536.1 C537.2

Not connected (* = marked no-connect by the designer): CN620 6; IC600 73 74 92

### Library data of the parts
C536-C538 C667 C668 C675 C685-C692 = C: OriginalSymbolOrigin: (2540,7620)
CN530 = C2A: as CN5 on sheet 1
CN620 = C14D: SAVEAREA0: -12827,-359,38319,30760; TIME: 17:50:57; UPDATEUSER: 19990028; UPDATETIME: 16:59:26; SAVECOUNT: 5; OriginalSymbolOrigin: (5080,27940); CDBNAME: CN
DS510 DS530 = LED: SAVEAREA0: -6799,-183,19247,15664; TIME: 14:49:55; UPDATEUSER: fukuda-y; UPDATETIME: 13:54:07; SAVECOUNT: 4; OriginalSymbolOrigin: (5080,7620); VAL3: KB_DELPS2.12; CDBNAME: DS
DS511 DS512 DS531 DS532 = LED: SAVEAREA0: -6799,-183,19247,15664; TIME: 14:49:55; UPDATEUSER: fukuda-y; UPDATETIME: 13:54:07; SAVECOUNT: 4; OriginalSymbolOrigin: (5080,7620); VAL3: KT_DELQS1.12; CDBNAME: DS
DS513 DS533 = LED: SAVEAREA0: -6799,-183,19247,15664; TIME: 14:49:55; UPDATEUSER: fukuda-y; UPDATETIME: 13:54:07; SAVECOUNT: 4; OriginalSymbolOrigin: (5080,7620); VAL3: KS_DELQS1.12; CDBNAME: DS
IC600 = TMS320F28377SPTP_1: TIME: 14:21:47; UPDATEUSER: sptcae13; UPDATETIME: 11:28:17; SAVECOUNT: 25; SAVEAREA0: -262105,-202108,136518,16016; OriginalSymbolOrigin: (7620,0); CaptureCellPackProp: TMS320F28377SPTP_1B; USERCOMPTEXT3: TOSHIBA; COMPONENTNAME: TMS320F28377SPTP_2; CDBNAME: IC
Q510 Q511 Q530 = RN1907_Q1: 7TH PART FIELD: RES.,; 4TH PART FIELD: VISHAY,; 3RD PART FIELD: CHIP; 2ND PART FIELD: 1-5%; 5TH PART FIELD: CRCW0805---RT6; 1ST PART FIELD: 1/8W; PARTS: 1; VAL1: VALUE; TIME: 08:44:45; UPDATEUSER: t4887876; UPDATETIME: 18:58:36; SAVECOUNT: 11; CLASS: DISCRETE; HETERO: RN4905_1,RN4905_2; FUNCTION: PNP&NPN_PCT; LEVEL: STD; PKG_TYPE: 2-2J1A; DEVICE: RN4905; SAVEAREA0: -13854,-30480,41847,0; DEVICENAME: DTC144EETL; OriginalSymbolOrigin: (0,12700); CaptureCellPackProp: RN1907_Q1A; COMPONENTNAME: RN1907_1
Q531 = RN1907_Q1: 7TH PART FIELD: RES.,; 4TH PART FIELD: VISHAY,; 3RD PART FIELD: CHIP; 2ND PART FIELD: 1-5%; 5TH PART FIELD: CRCW0805---RT6; 1ST PART FIELD: 1/8W; PARTS: 1; VAL1: VALUE; TIME: 08:44:45; UPDATEUSER: t4887876; UPDATETIME: 18:58:36; SAVECOUNT: 11; CLASS: DISCRETE; HETERO: RN4905_1,RN4905_2; FUNCTION: PNP&NPN_PCT; LEVEL: STD; PKG_TYPE: 2-2J1A; DEVICE: RN4905; SAVEAREA0: -13854,-30480,41847,0; DEVICENAME: DTC144EETL; OriginalSymbolOrigin: (0,12700); CaptureCellPackProp: RN1907_Q1A; FUNCN: RN1907_1
Q532 = TRN: as Q512 on sheet 1
R507 R508 R516-R519 R524 R534-R539 R589 R613 R614 R618 R620 R656-R659 R669 = R: as R506 on sheet 1
R584 = R: as R564 on sheet 1
R585-R588 = R: as R565 on sheet 1
U?#2 = WAKU_DEF_A3: PLOTTIME: HH:MM; SAVEAREA0: 96913,-567914,509243,-368858; TIME: 08:03:34; UPDATEUSER: t5459927; UPDATETIME: 13:38:15; SAVECOUNT: 19; ZONEOFFSETX: 36; ZONEOFFSETY: -24; OriginalSymbolOrigin: (12700,-12700); SHTSAVECOUNT: 79

## Sheet 3.SchDoc
size 609 x 444 mm
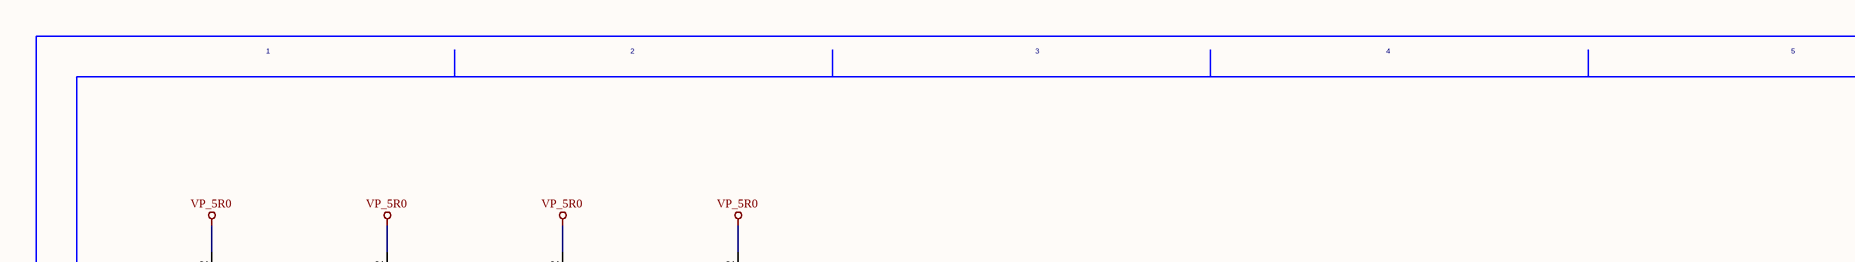
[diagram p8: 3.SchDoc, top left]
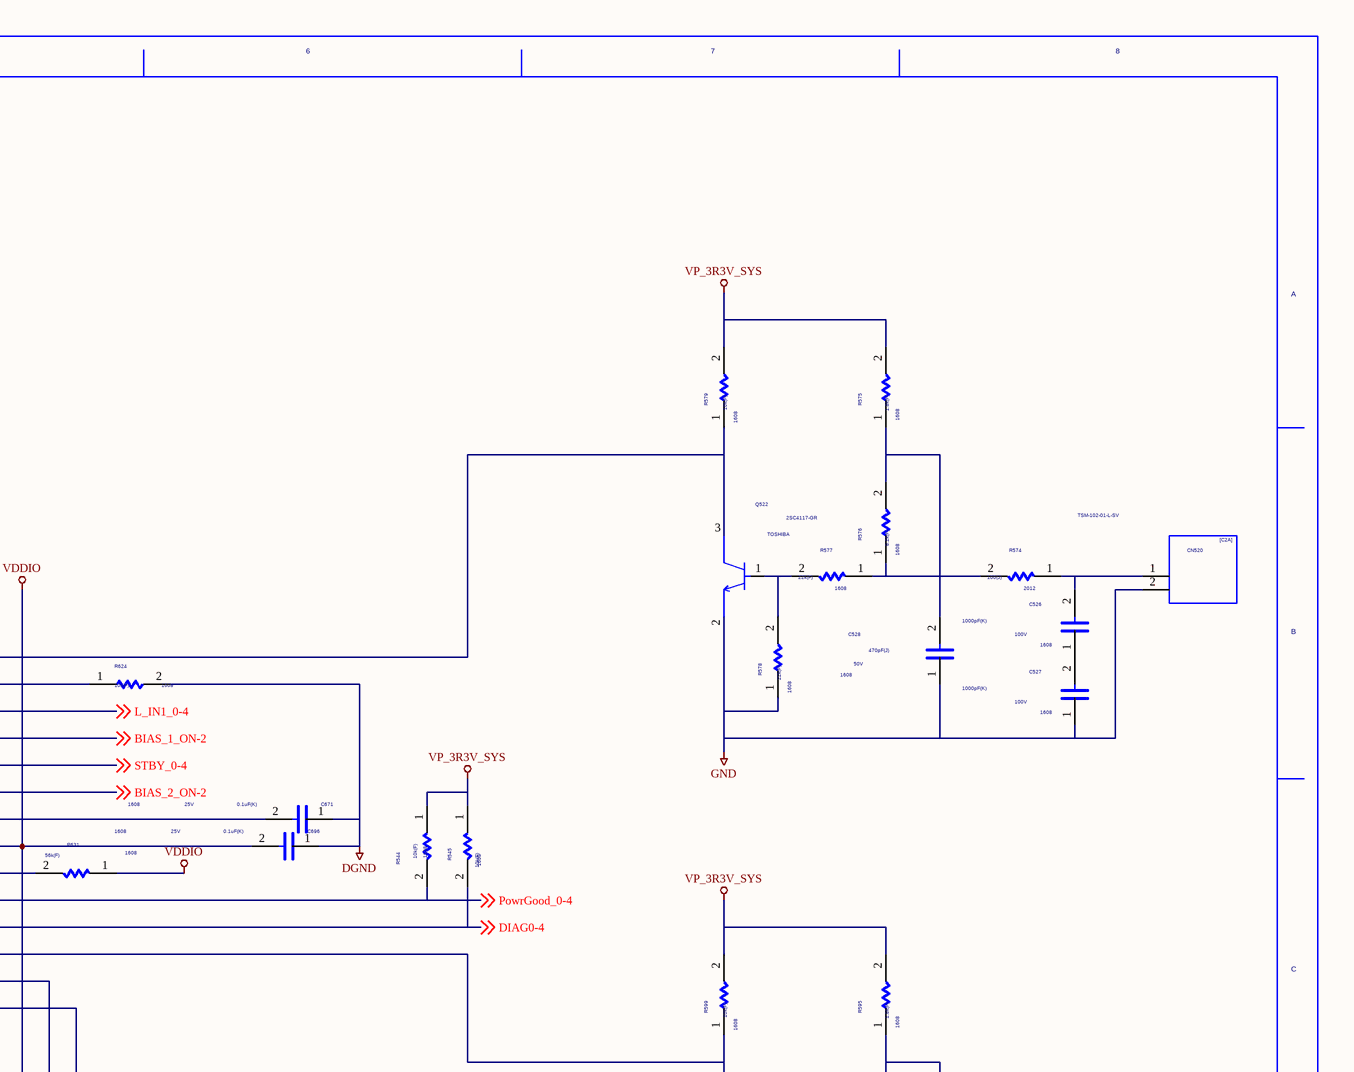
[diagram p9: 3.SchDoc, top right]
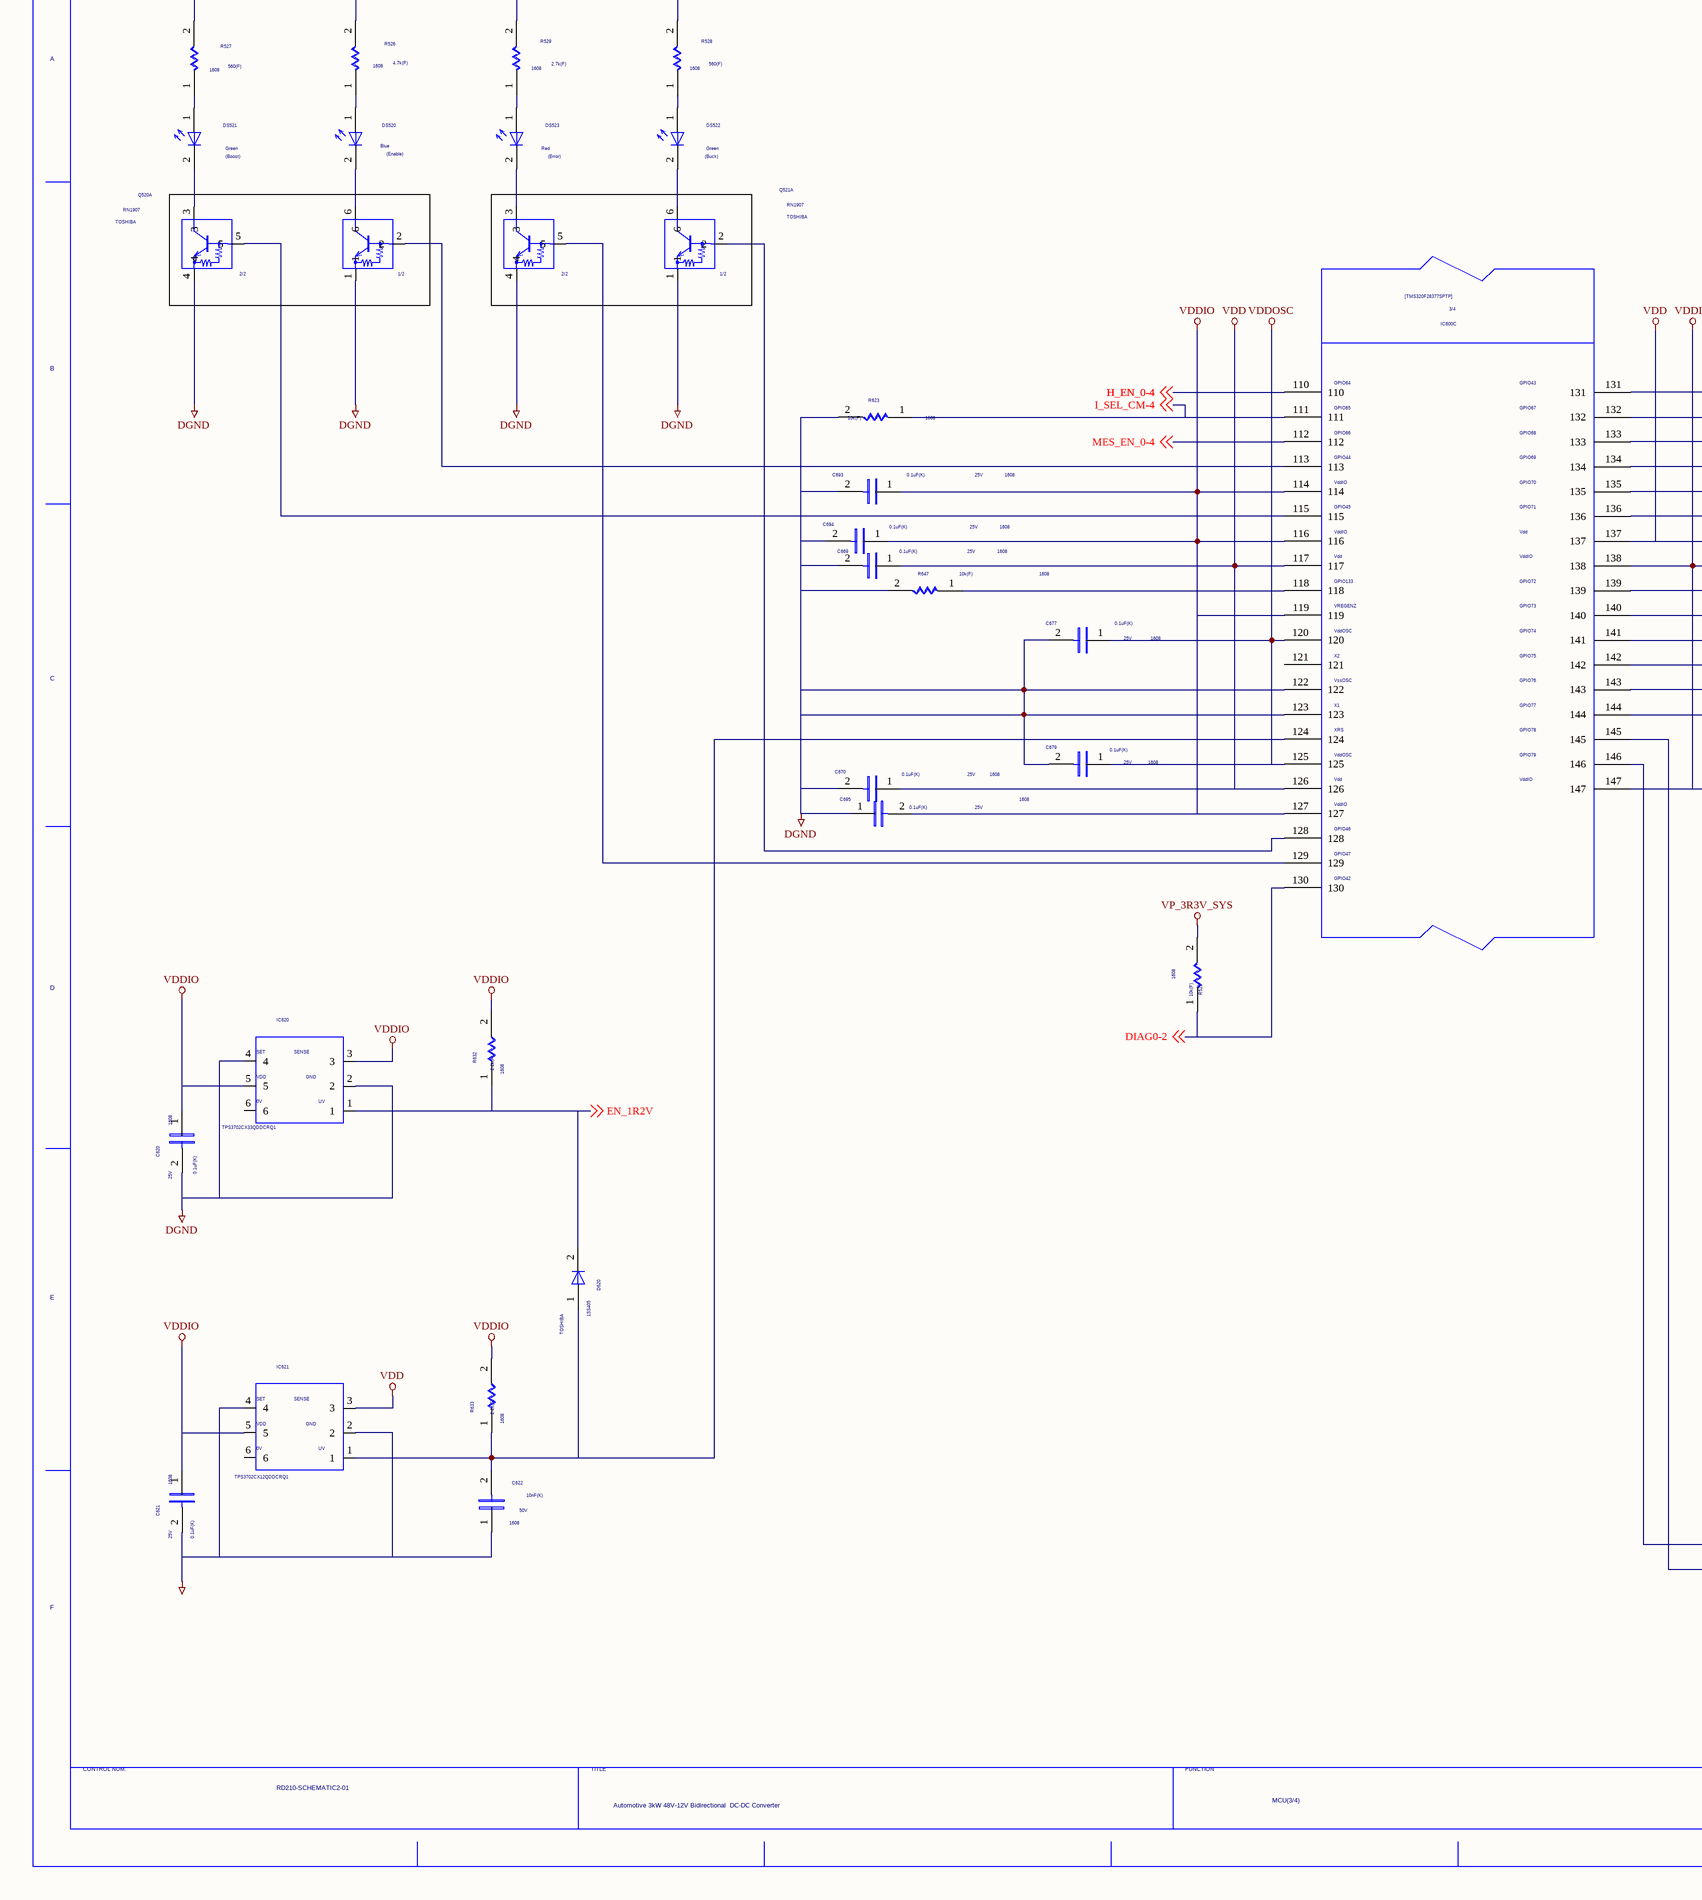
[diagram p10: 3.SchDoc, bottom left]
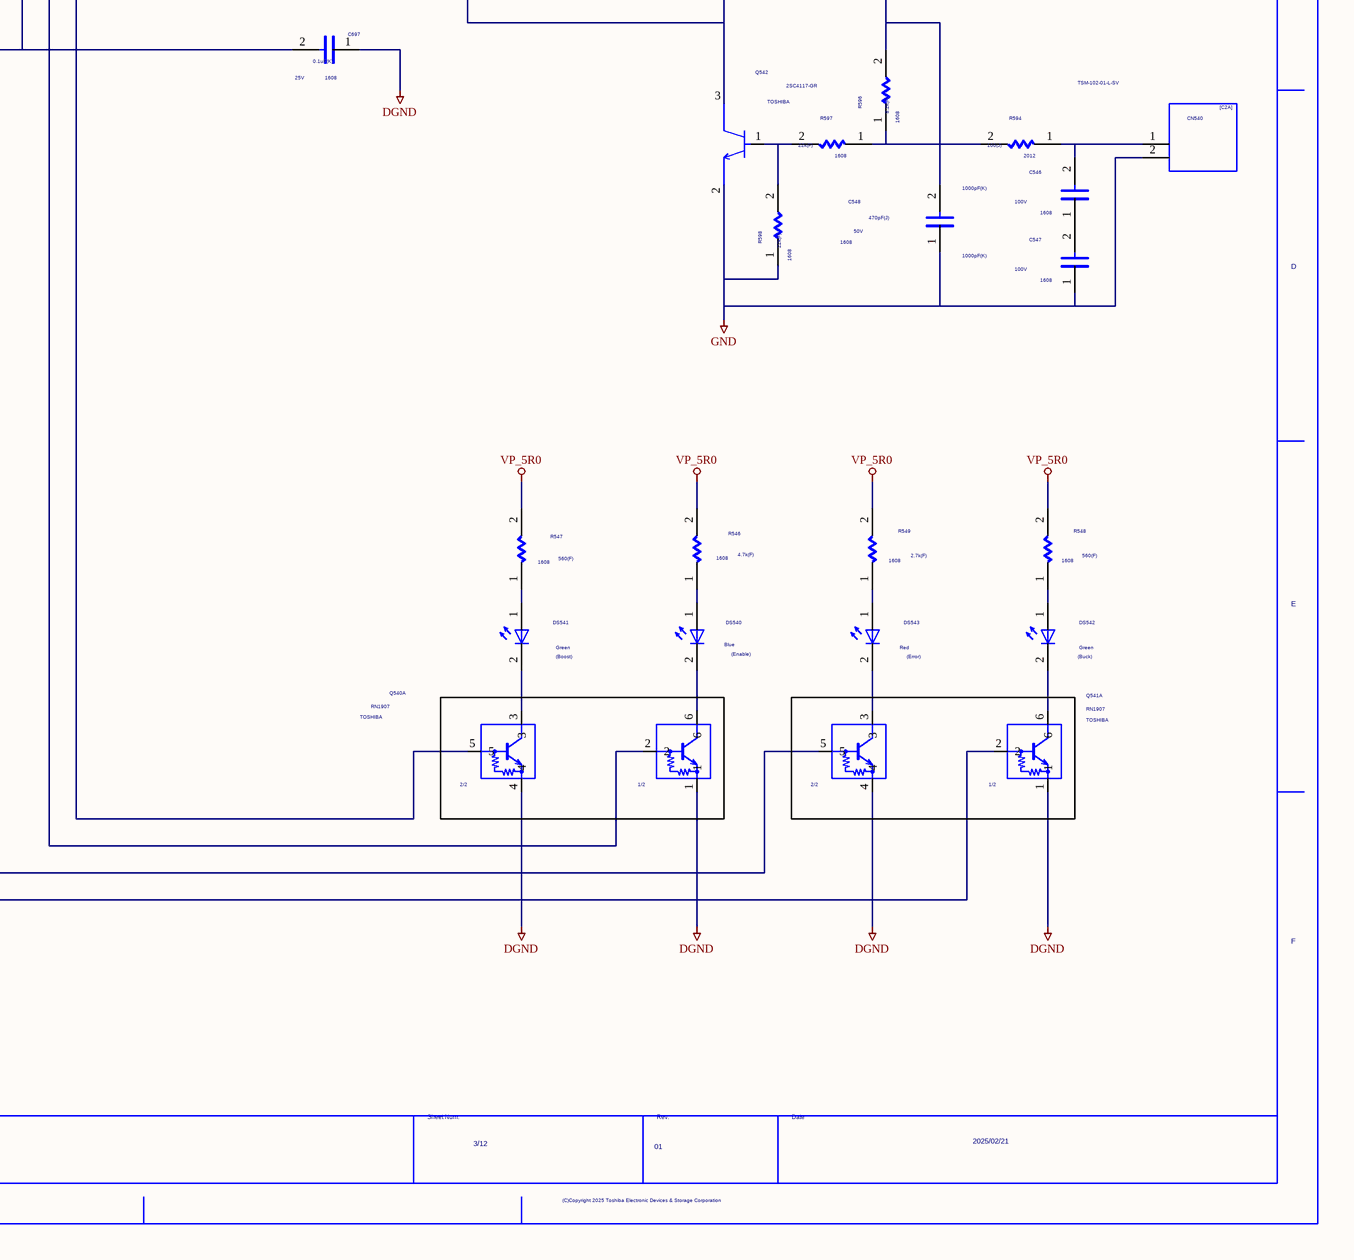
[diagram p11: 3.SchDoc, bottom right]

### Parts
(Parts that share a designator on the sheet are numbered #1, #2 ... from top to bottom, then left to right.)
C526  VAL1: 1000pF(K)  VAL2: 100V  SIZECODESMD: 1608  (hidden comment: C)
C527  VAL1: 1000pF(K)  VAL2: 100V  SIZECODESMD: 1608  (hidden comment: C)
C528  VAL1: 470pF(J)  VAL2: 50V  SIZECODESMD: 1608  (hidden comment: C)
C546  VAL1: 1000pF(K)  VAL2: 100V  SIZECODESMD: 1608  (hidden comment: C)
C547  VAL1: 1000pF(K)  VAL2: 100V  SIZECODESMD: 1608  (hidden comment: C)
C548  VAL1: 470pF(J)  VAL2: 50V  SIZECODESMD: 1608  (hidden comment: C)
C620  VAL1: 0.1uF(K)  VAL2: 25V  SIZECODESMD: 1608  (hidden comment: C)
C621  VAL1: 0.1uF(K)  VAL2: 25V  SIZECODESMD: 1608  (hidden comment: C)
C622  VAL1: 10nF(K)  VAL2: 50V  SIZECODESMD: 1608  (hidden comment: C)
C669  VAL1: 0.1uF(K)  VAL2: 25V  SIZECODESMD: 1608  (hidden comment: C)
C670  VAL1: 0.1uF(K)  VAL2: 25V  SIZECODESMD: 1608  (hidden comment: C)
C671  VAL1: 0.1uF(K)  VAL2: 25V  SIZECODESMD: 1608  (hidden comment: C)
C677  VAL1: 0.1uF(K)  VAL2: 25V  SIZECODESMD: 1608  (hidden comment: C)
C679  VAL1: 0.1uF(K)  VAL2: 25V  SIZECODESMD: 1608  (hidden comment: C)
C693  VAL1: 0.1uF(K)  VAL2: 25V  SIZECODESMD: 1608  (hidden comment: C)
C694  VAL1: 0.1uF(K)  VAL2: 25V  SIZECODESMD: 1608  (hidden comment: C)
C695  VAL1: 0.1uF(K)  VAL2: 25V  SIZECODESMD: 1608  (hidden comment: C)
C696  VAL1: 0.1uF(K)  VAL2: 25V  SIZECODESMD: 1608  (hidden comment: C)
C697  VAL1: 0.1uF(K)  VAL2: 25V  SIZECODESMD: 1608  (hidden comment: C)
CN520  VAL3: TSM-102-01-L-SV  (hidden comment: C2A)
CN540  VAL3: TSM-102-01-L-SV  (hidden comment: C2A)
D620  USERCOMPTEXT3: TOSHIBA  VAL3: 1SS405  (hidden comment: D)
DS520  VAL1: Blue  USERCOMPTEXT1: (Enable)  (hidden comment: LED)
DS521  VAL1: Green  USERCOMPTEXT1: (Boost)  (hidden comment: LED)
DS522  VAL1: Green  USERCOMPTEXT1: (Buck)  (hidden comment: LED)
DS523  VAL1: Red  USERCOMPTEXT1: (Error)  (hidden comment: LED)
DS540  VAL1: Blue  USERCOMPTEXT1: (Enable)  (hidden comment: LED)
DS541  VAL1: Green  USERCOMPTEXT1: (Boost)  (hidden comment: LED)
DS542  VAL1: Green  USERCOMPTEXT1: (Buck)  (hidden comment: LED)
DS543  VAL1: Red  USERCOMPTEXT1: (Error)  (hidden comment: LED)
IC600  TMS320F28377SPTP_1  (value not drawn)  (part C of 4)
IC620  VAL3: TPS3702CX33QDDCRQ1  (hidden comment: TPS3702CX12QDDCRQ1)
IC621  TPS3702CX12QDDCRQ1
Q520  USERCOMPTEXT1: 1/2  USERCOMPTEXT3: TOSHIBA  VAL3: RN1907  (hidden comment: RN1907_Q1)  (parts A,B of 2)
Q521  USERCOMPTEXT1: 1/2  USERCOMPTEXT3: TOSHIBA  VAL3: RN1907  (hidden comment: RN1907_Q1)  (parts A,B of 2)
Q522  USERCOMPTEXT3: TOSHIBA  VAL3: 2SC4117-GR  (hidden comment: TRN)
Q540  USERCOMPTEXT1: 1/2  USERCOMPTEXT3: TOSHIBA  VAL3: RN1907  (hidden comment: RN1907_Q1)  (parts A,B of 2)
Q541  USERCOMPTEXT1: 1/2  USERCOMPTEXT3: TOSHIBA  VAL3: RN1907  (hidden comment: RN1907_Q1)  (parts A,B of 2)
Q542  USERCOMPTEXT3: TOSHIBA  VAL3: 2SC4117-GR  (hidden comment: TRN)
R525  VAL1: 10k(F)  SIZECODESMD: 1608  (hidden comment: R)
R526  VAL1: 4.7k(F)  SIZECODESMD: 1608  (hidden comment: R)
R527  VAL1: 560(F)  SIZECODESMD: 1608  (hidden comment: R)
R528  VAL1: 560(F)  SIZECODESMD: 1608  (hidden comment: R)
R529  VAL1: 2.7k(F)  SIZECODESMD: 1608  (hidden comment: R)
R544  VAL1: 10k(F)  SIZECODESMD: 1608  (hidden comment: R)
R545  VAL1: 10k(F)  SIZECODESMD: 1608  (hidden comment: R)
R546  VAL1: 4.7k(F)  SIZECODESMD: 1608  (hidden comment: R)
R547  VAL1: 560(F)  SIZECODESMD: 1608  (hidden comment: R)
R548  VAL1: 560(F)  SIZECODESMD: 1608  (hidden comment: R)
R549  VAL1: 2.7k(F)  SIZECODESMD: 1608  (hidden comment: R)
R574  VAL1: 100(J)  SIZECODESMD: 2012  (hidden comment: R)
R575  VAL1: 1.8k(F)  SIZECODESMD: 1608  (hidden comment: R)
R576  VAL1: 8.2k(F)  SIZECODESMD: 1608  (hidden comment: R)
R577  VAL1: 22k(F)  SIZECODESMD: 1608  (hidden comment: R)
R578  VAL1: 22k(F)  SIZECODESMD: 1608  (hidden comment: R)
R579  VAL1: 10k(F)  SIZECODESMD: 1608  (hidden comment: R)
R594  VAL1: 100(J)  SIZECODESMD: 2012  (hidden comment: R)
R595  VAL1: 1.8k(F)  SIZECODESMD: 1608  (hidden comment: R)
R596  VAL1: 8.2k(F)  SIZECODESMD: 1608  (hidden comment: R)
R597  VAL1: 22k(F)  SIZECODESMD: 1608  (hidden comment: R)
R598  VAL1: 22k(F)  SIZECODESMD: 1608  (hidden comment: R)
R599  VAL1: 10k(F)  SIZECODESMD: 1608  (hidden comment: R)
R623  VAL1: 10k(F)  SIZECODESMD: 1608  (hidden comment: R)
R624  VAL1: 10k(F)  SIZECODESMD: 1608  (hidden comment: R)
R631  VAL1: 56k(F)  SIZECODESMD: 1608  (hidden comment: R)
R632  VAL1: 2.2k(F)  SIZECODESMD: 1608  (hidden comment: R)
R633  VAL1: 2.2k(F)  SIZECODESMD: 1608  (hidden comment: R)
R647  VAL1: 10k(F)  SIZECODESMD: 1608  (hidden comment: R)
U?#3  DATE: 2025/02/21  DRAWINGNUMBER: RD210-SCHEMATIC2-01  TITLE: Automotive 3kW 48V-12V Bidirectional / DC-DC Converter  FUNCTION: MCU(3/4)  SHEETNUMBER: 3/12  REVISION: 01  (hidden comment: WAKU_DEF_A3)

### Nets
DGND: C620.2 C621.2 C622.1 C669.2 C670.2 C671.1 C677.2 C679.2 C693.2 C694.2 C695.1 C696.1 C697.1 IC600.122 IC600.123 IC620.2 IC620.4 IC621.2 IC621.4 Q520.1 Q520.4 Q521.1 Q521.4 Q540.1 Q540.4 Q541.1 Q541.4 R623.2 R624.2 R647.2
GND: C527.1 C528.1 C547.1 C548.1 CN520.2 CN540.2 Q522.2(E) Q542.2(E) R578.1 R598.1
VDD: C669.1 C670.1 C671.2 IC600.117 IC600.126 IC600.137 IC621.3
VDDIO: C620.1 C621.1 C693.1 C694.1 C695.2 C696.2 C697.2 IC600.114 IC600.116 IC600.119 IC600.127 IC600.138 IC600.147 IC620.3 IC620.5 IC621.5 R631.1 R632.2 R633.2
VDDOSC: C677.1 C679.1 IC600.120 IC600.125
VP_3R3V_SYS: R525.2 R544.1 R545.1 R575.2 R579.2 R595.2 R599.2
VP_5R0: R526.2 R527.2 R528.2 R529.2 R546.2 R547.2 R548.2 R549.2
BIAS_1_ON-2: IC600.134 ; off-sheet BIAS_1_ON-2
BIAS_2_ON-2: IC600.136 ; off-sheet BIAS_2_ON-2
DIAG0-2: IC600.130 R525.1 ; off-sheet DIAG0-2
DIAG0-4: IC600.141 R545.2 ; off-sheet DIAG0-4
EN_1R2V: D620.2(C) IC620.1 R632.1 ; off-sheet EN_1R2V
H_EN_0-4: IC600.110 ; off-sheet H_EN_0-4
I_SEL_CM-4: IC600.111 R623.1 ; off-sheet I_SEL_CM-4
L_IN1_0-4: IC600.133 ; off-sheet L_IN1_0-4
MES_EN_0-4: IC600.112 ; off-sheet MES_EN_0-4
PowrGood_0-4: IC600.140 R544.2 ; off-sheet PowrGood_0-4
SIG0034: DS540.2(C) Q540.6
SIG0036: DS542.2(C) Q541.6
SIG0037: DS540.1(A) R546.1
SIG0038: DS543.1(A) R549.1
SIG0039: DS542.1(A) R548.1
SIG00310: DS541.1(A) R547.1
SIG00311: DS543.2(C) Q541.3
SIG00313: DS541.2(C) Q540.3
SIG00314: IC600.144 Q540.5
SIG00315: IC600.143 Q540.2
SIG00316: IC600.146 Q541.5
SIG00317: IC600.145 Q541.2
SIG00319: C546.2 CN540.1 R594.1
SIG00320: Q542.1(B) R597.2 R598.2
SIG00321: C548.2 R595.1 R596.2
SIG00323: R594.2 R596.1 R597.1
SIG00325: Q522.1(B) R577.2 R578.2
SIG00326: C526.2 CN520.1 R574.1
SIG00328: C528.2 R575.1 R576.2
SIG00329: R574.2 R576.1 R577.1
SIG00330: IC600.142 Q542.3(C) R599.1
SIG00331: IC600.131 Q522.3(C) R579.1
SIG00337: DS521.1(A) R527.1
SIG00339: DS520.1(A) R526.1
SIG00340: DS523.2(C) Q521.3
SIG00342: DS521.2(C) Q520.3
SIG00343: DS520.2(C) Q520.6
SIG00344: DS522.1(A) R528.1
SIG00345: DS523.1(A) R529.1
SIG00346: DS522.2(C) Q521.6
SIG00348: IC600.115 Q520.5
SIG00349: IC600.113 Q520.2
SIG00350: IC600.129 Q521.5
SIG00351: IC600.128 Q521.2
SIG00354: C622.2 D620.1(A) IC600.124 IC621.1 R633.1
SIG738: IC600.118 R647.1
SIG779: IC600.132 R624.1
SIG780: IC600.139 R631.2
STBY_0-4: IC600.135 ; off-sheet STBY_0-4
NetC526_1: C526.1 C527.2
NetC546_1: C546.1 C547.2

Not connected (* = marked no-connect by the designer): IC600 121; IC620 6; IC621 6

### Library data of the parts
C526-C528 C546-C548 C620-C622 C669-C671 C677 C679 C693-C697 = C: OriginalSymbolOrigin: (2540,7620)
CN520 CN540 = C2A: as CN5 on sheet 1
D620 = D: SAVEAREA0: -225,-91,12804,7836; SAVECOUNT: 3; TIME: 14:49:55; UPDATEUSER: 19870035; UPDATETIME: 14:20:16; OriginalSymbolOrigin: (5080,5080)
DS520 DS540 = LED: as DS510 on sheet 2
DS521 DS522 DS541 DS542 = LED: as DS511 on sheet 2
DS523 DS543 = LED: as DS513 on sheet 2
IC600 = TMS320F28377SPTP_1: TIME: 14:21:47; UPDATEUSER: sptcae13; UPDATETIME: 11:28:17; SAVECOUNT: 36; SAVEAREA0: -107962,-126732,184126,6359; OriginalSymbolOrigin: (7620,0); CaptureCellPackProp: TMS320F28377SPTP_1C; USERCOMPTEXT3: TOSHIBA; COMPONENTNAME: TMS320F28377SPTP_3; CDBNAME: IC
IC620 IC621 = TPS3702CX12QDDCRQ1: MANUFACTURER: PHOENIX CONTACT; ITEM: Connector 2Pin Terminal Block; COMP: IC; SCH_NAME: MCV1,5/2-G-3.5; ゴン長さ: Short; TIME: 08:44:48; UPDATEUSER: sptcae13; UPDATETIME: 14:58:53; SAVECOUNT: 4; SAVEAREA0: -8061,-17780,30959,0; OriginalSymbolOrigin: (2540,0)
Q520 Q521 Q540 Q541 = RN1907_Q1: as Q510 on sheet 2
Q522 Q542 = TRN: as Q512 on sheet 1
R525-R529 R544-R549 R579 R599 R623 R624 R631-R633 R647 = R: as R506 on sheet 1
R574 R594 = R: as R564 on sheet 1
R575-R578 R595-R598 = R: as R565 on sheet 1
U?#3 = WAKU_DEF_A3: PLOTTIME: HH:MM; SAVEAREA0: 96913,-567914,509243,-368858; TIME: 08:03:34; UPDATEUSER: t5459927; UPDATETIME: 12:28:01; SAVECOUNT: 19; ZONEOFFSETX: 36; ZONEOFFSETY: -24; OriginalSymbolOrigin: (12700,-12700); SHTSAVECOUNT: 66

## Sheet 4.SchDoc
size 609 x 444 mm
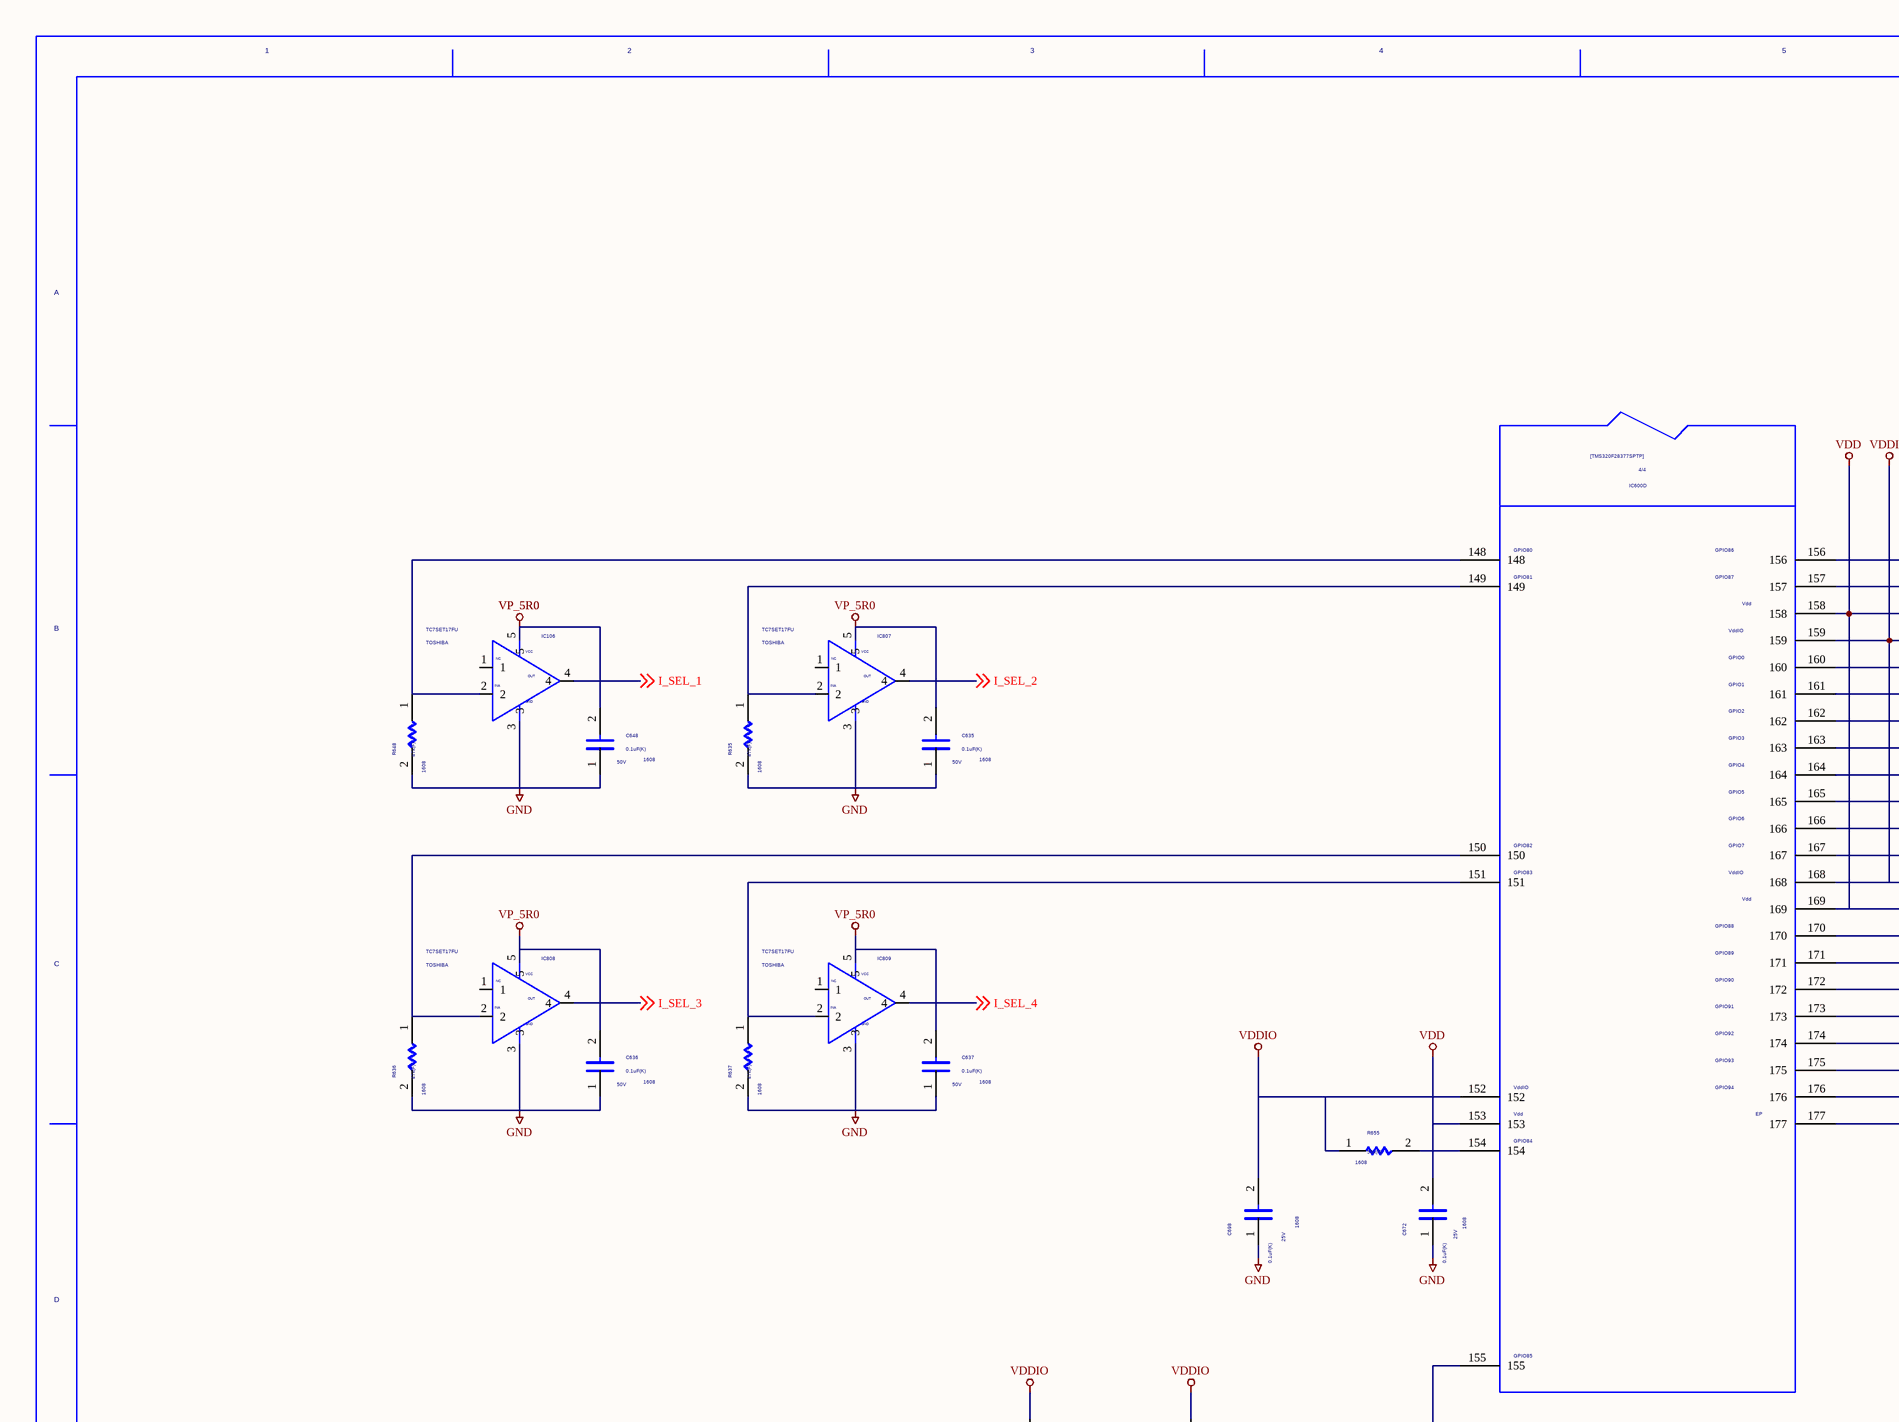
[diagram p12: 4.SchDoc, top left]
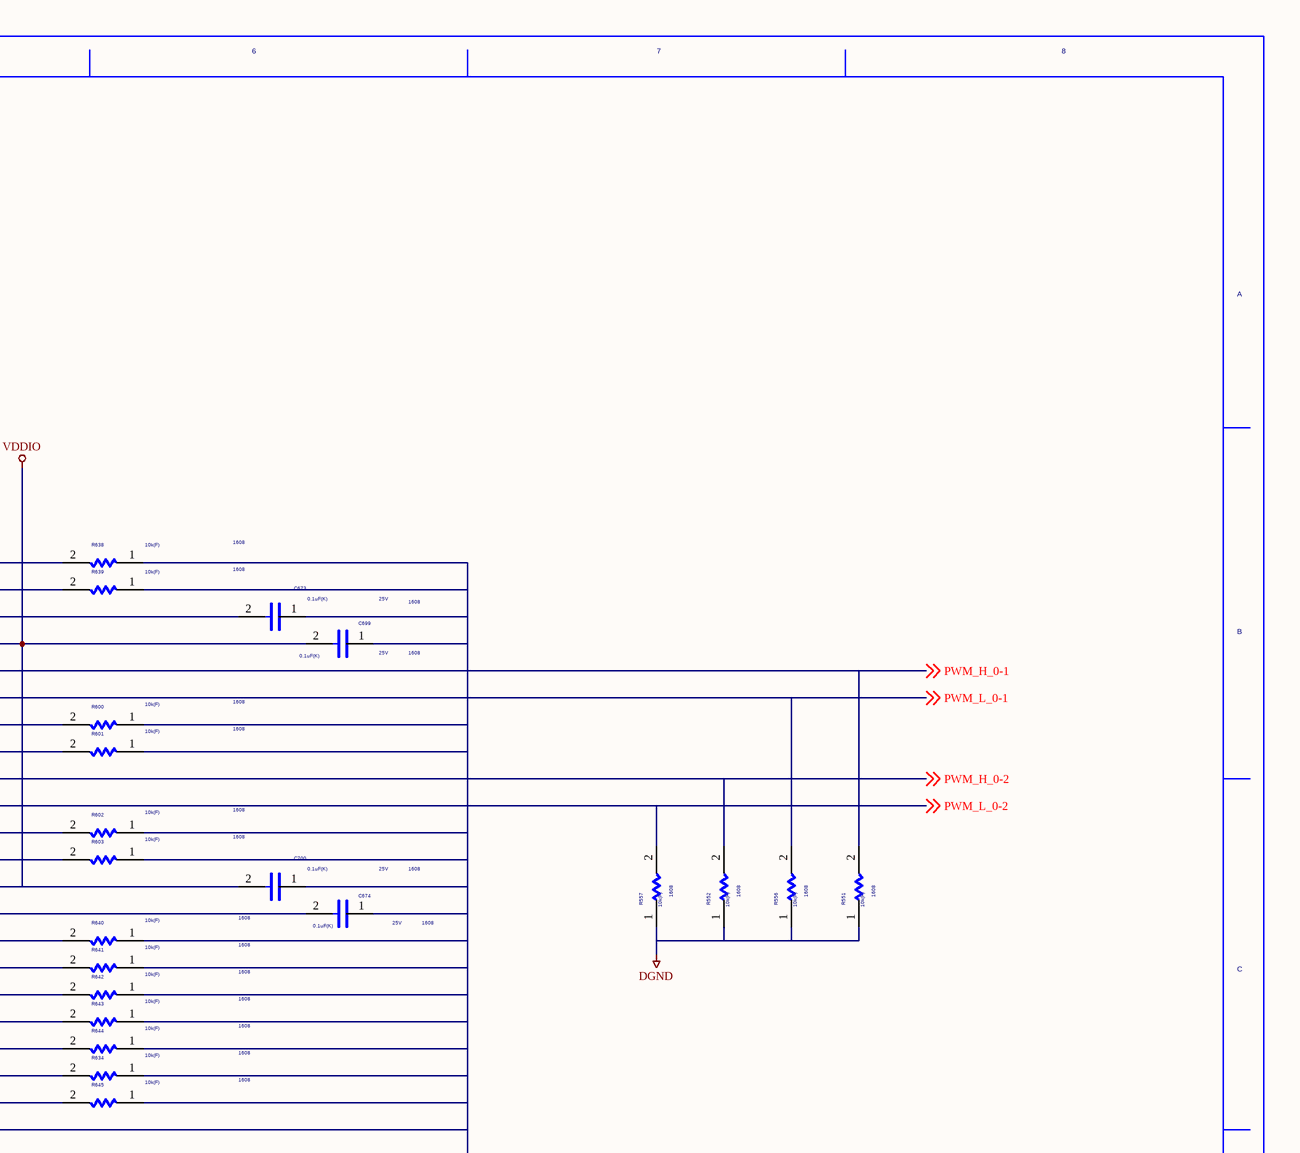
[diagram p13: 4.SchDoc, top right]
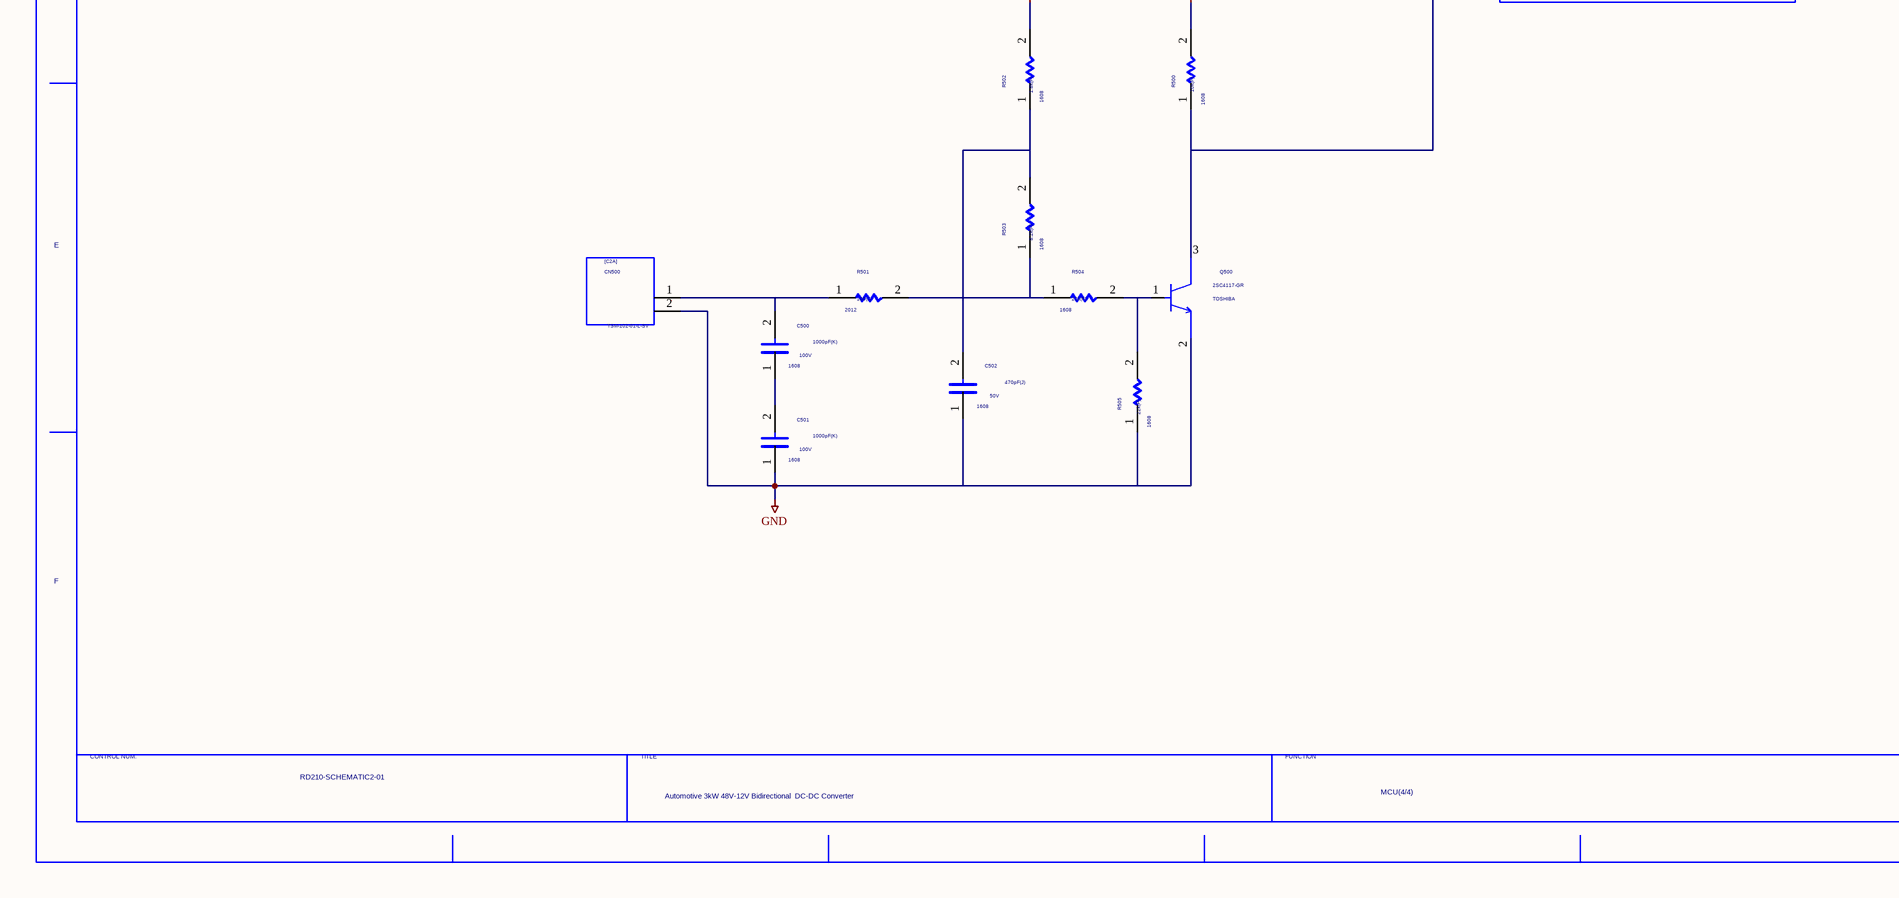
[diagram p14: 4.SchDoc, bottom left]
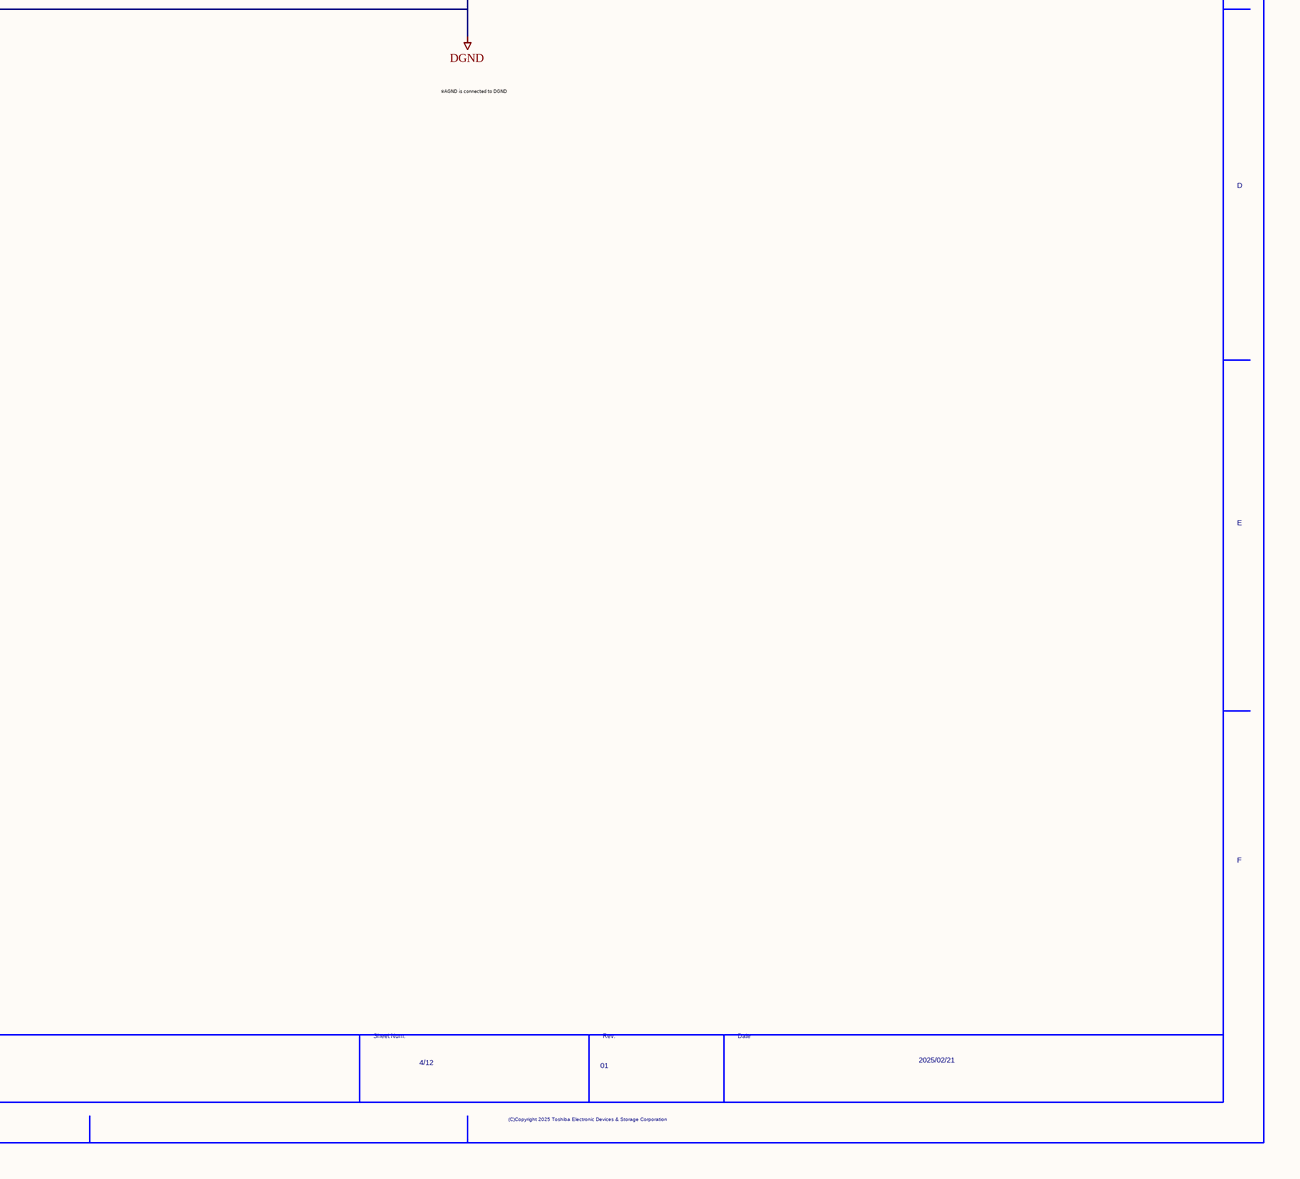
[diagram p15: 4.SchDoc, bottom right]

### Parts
(Parts that share a designator on the sheet are numbered #1, #2 ... from top to bottom, then left to right.)
C500  VAL1: 1000pF(K)  VAL2: 100V  SIZECODESMD: 1608  (hidden comment: C)
C501  VAL1: 1000pF(K)  VAL2: 100V  SIZECODESMD: 1608  (hidden comment: C)
C502  VAL1: 470pF(J)  VAL2: 50V  SIZECODESMD: 1608  (hidden comment: C)
C635  VAL1: 0.1uF(K)  VAL2: 50V  SIZECODESMD: 1608  (hidden comment: C)
C636  VAL1: 0.1uF(K)  VAL2: 50V  SIZECODESMD: 1608  (hidden comment: C)
C637  VAL1: 0.1uF(K)  VAL2: 50V  SIZECODESMD: 1608  (hidden comment: C)
C648  VAL1: 0.1uF(K)  VAL2: 50V  SIZECODESMD: 1608  (hidden comment: C)
C672  VAL1: 0.1uF(K)  VAL2: 25V  SIZECODESMD: 1608  (hidden comment: C)
C673  VAL1: 0.1uF(K)  VAL2: 25V  SIZECODESMD: 1608  (hidden comment: C)
C674  VAL1: 0.1uF(K)  VAL2: 25V  SIZECODESMD: 1608  (hidden comment: C)
C698  VAL1: 0.1uF(K)  VAL2: 25V  SIZECODESMD: 1608  (hidden comment: C)
C699  VAL1: 0.1uF(K)  VAL2: 25V  SIZECODESMD: 1608  (hidden comment: C)
C700  VAL1: 0.1uF(K)  VAL2: 25V  SIZECODESMD: 1608  (hidden comment: C)
CN500  VAL3: TSM-102-01-L-SV  (hidden comment: C2A)
IC106  USERCOMPTEXT3: TOSHIBA  (hidden comment: TC7SET17FU)
IC600  TMS320F28377SPTP_1  (value not drawn)  (part D of 4)
IC807  USERCOMPTEXT3: TOSHIBA  (hidden comment: TC7SET17FU)
IC808  USERCOMPTEXT3: TOSHIBA  (hidden comment: TC7SET17FU)
IC809  USERCOMPTEXT3: TOSHIBA  (hidden comment: TC7SET17FU)
Q500  USERCOMPTEXT3: TOSHIBA  VAL3: 2SC4117-GR  (hidden comment: TRN)
R500  VAL1: 10k(F)  SIZECODESMD: 1608  (hidden comment: R)
R501  VAL1: 100(J)  SIZECODESMD: 2012  (hidden comment: R)
R502  VAL1: 1.8k(F)  SIZECODESMD: 1608  (hidden comment: R)
R503  VAL1: 8.2k(F)  SIZECODESMD: 1608  (hidden comment: R)
R504  VAL1: 22k(F)  SIZECODESMD: 1608  (hidden comment: R)
R505  VAL1: 22k(F)  SIZECODESMD: 1608  (hidden comment: R)
R551  VAL1: 10k(F)  SIZECODESMD: 1608  (hidden comment: R)
R552  VAL1: 10k(F)  SIZECODESMD: 1608  (hidden comment: R)
R556  VAL1: 10k(F)  SIZECODESMD: 1608  (hidden comment: R)
R557  VAL1: 10k(F)  SIZECODESMD: 1608  (hidden comment: R)
R600  VAL1: 10k(F)  SIZECODESMD: 1608  (hidden comment: R)
R601  VAL1: 10k(F)  SIZECODESMD: 1608  (hidden comment: R)
R602  VAL1: 10k(F)  SIZECODESMD: 1608  (hidden comment: R)
R603  VAL1: 10k(F)  SIZECODESMD: 1608  (hidden comment: R)
R634  VAL1: 10k(F)  SIZECODESMD: 1608  (hidden comment: R)
R635  VAL1: 47k(F)  SIZECODESMD: 1608  (hidden comment: R)
R636  VAL1: 47k(F)  SIZECODESMD: 1608  (hidden comment: R)
R637  VAL1: 47k(F)  SIZECODESMD: 1608  (hidden comment: R)
R638  VAL1: 10k(F)  SIZECODESMD: 1608  (hidden comment: R)
R639  VAL1: 10k(F)  SIZECODESMD: 1608  (hidden comment: R)
R640  VAL1: 10k(F)  SIZECODESMD: 1608  (hidden comment: R)
R641  VAL1: 10k(F)  SIZECODESMD: 1608  (hidden comment: R)
R642  VAL1: 10k(F)  SIZECODESMD: 1608  (hidden comment: R)
R643  VAL1: 10k(F)  SIZECODESMD: 1608  (hidden comment: R)
R644  VAL1: 10k(F)  SIZECODESMD: 1608  (hidden comment: R)
R645  VAL1: 10k(F)  SIZECODESMD: 1608  (hidden comment: R)
R648  VAL1: 47k(F)  SIZECODESMD: 1608  (hidden comment: R)
R655  VAL1: 56k(F)  SIZECODESMD: 1608  (hidden comment: R)
U?#4  DATE: 2025/02/21  DRAWINGNUMBER: RD210-SCHEMATIC2-01  TITLE: Automotive 3kW 48V-12V Bidirectional / DC-DC Converter  FUNCTION: MCU(4/4)  SHEETNUMBER: 4/12  REVISION: 01  (hidden comment: WAKU_DEF_A3)

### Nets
DGND: C673.1 C674.1 C699.1 C700.1 IC600.177 R551.1 R552.1 R556.1 R557.1 R600.1 R601.1 R602.1 R603.1 R634.1 R638.1 R639.1 R640.1 R641.1 R642.1 R643.1 R644.1 R645.1
GND: C501.1 C502.1 C635.1 C636.1 C637.1 C648.1 C672.1 C698.1 CN500.2 IC106.3 IC807.3 IC808.3 IC809.3 Q500.2(E) R505.1 R635.2 R636.2 R637.2 R648.2
VDD: C672.2 C673.2 C674.2 IC600.153 IC600.158 IC600.169
VDDIO: C698.2 C699.2 C700.2 IC600.152 IC600.159 IC600.168 R500.2 R502.2 R655.1
VP_5R0: C635.2 C636.2 C637.2 C648.2 IC106.5 IC807.5 IC808.5 IC809.5
I_SEL_1: IC106.4 ; off-sheet I_SEL_1
I_SEL_2: IC807.4 ; off-sheet I_SEL_2
I_SEL_3: IC808.4 ; off-sheet I_SEL_3
I_SEL_4: IC809.4 ; off-sheet I_SEL_4
PWM_H_0-1: IC600.160 R551.2 ; off-sheet PWM_H_0-1
PWM_H_0-2: IC600.164 R552.2 ; off-sheet PWM_H_0-2
PWM_L_0-1: IC600.161 R556.2 ; off-sheet PWM_L_0-1
PWM_L_0-2: IC600.165 R557.2 ; off-sheet PWM_L_0-2
SIG0042: Q500.1(B) R504.2 R505.2
SIG0043: C502.2 R502.1 R503.2
SIG0044: C500.1 C501.2
SIG0045: C500.2 CN500.1 R501.1
SIG0047: R501.2 R503.1 R504.1
SIG0048: IC600.155 Q500.3(C) R500.1
SIG819: IC106.2 IC600.148 R648.1
SIG825: IC600.149 IC807.2 R635.1
SIG848: IC600.150 IC808.2 R636.1
SIG849: IC600.151 IC809.2 R637.1
SIG850: IC600.154 R655.2
SIG852: IC600.156 R638.2
SIG853: IC600.157 R639.2
SIG855: IC600.163 R601.2
SIG856: IC600.162 R600.2
SIG857: IC600.167 R603.2
SIG858: IC600.166 R602.2
SIG859: IC600.170 R640.2
SIG860: IC600.171 R641.2
SIG861: IC600.172 R642.2
SIG862: IC600.175 R634.2
SIG863: IC600.174 R644.2
SIG864: IC600.173 R643.2
SIG865: IC600.176 R645.2

Not connected (* = marked no-connect by the designer): IC106 1; IC807 1; IC808 1; IC809 1

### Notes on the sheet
- ※AGND is connected to DGND

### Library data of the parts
C500-C502 C635-C637 C648 C672-C674 C698-C700 = C: OriginalSymbolOrigin: (2540,7620)
CN500 = C2A: as CN5 on sheet 1
IC106 IC807-IC809 = TC7SET17FU: MANUFACTURER: WURTH; ITEM: Transformer; VAL2: Np:Ns1:Ns2:Ns3:Ns4:Naux=2.2:2:2:2:2:1; VAL1: 750342424; TIME: 08:44:46; UPDATEUSER: sptcae13; UPDATETIME: 17:58:26; SAVECOUNT: 5; SAVEAREA0: -63459,-44161,77282,32851; OriginalSymbolOrigin: (2540,0); CDBNAME: IC
IC600 = TMS320F28377SPTP_1: TIME: 14:21:47; UPDATEUSER: sptcae13; UPDATETIME: 11:28:17; SAVECOUNT: 36; SAVEAREA0: -167160,-242382,240591,56118; OriginalSymbolOrigin: (7620,0); CaptureCellPackProp: TMS320F28377SPTP_1D; USERCOMPTEXT3: TOSHIBA; COMPONENTNAME: TMS320F28377SPTP_4; CDBNAME: IC
Q500 = TRN: as Q512 on sheet 1
R500 R551 R552 R556 R557 R600-R603 R634 R638-R645 R655 = R: as R506 on sheet 1
R501 = R: as R564 on sheet 1
R502-R505 = R: as R565 on sheet 1
R635-R637 R648 = R: VAL2: 100mW; OriginalSymbolOrigin: (5080,5080)
U?#4 = WAKU_DEF_A3: PLOTTIME: HH:MM; SAVEAREA0: 96913,-567914,509243,-368858; TIME: 17:43:31; UPDATEUSER: t5459927; UPDATETIME: 06:43:32; SAVECOUNT: 8; ZONEOFFSETX: 36; ZONEOFFSETY: -24; OriginalSymbolOrigin: (12700,-12700); SHTSAVECOUNT: 41

## Sheet 5.SchDoc
size 609 x 444 mm
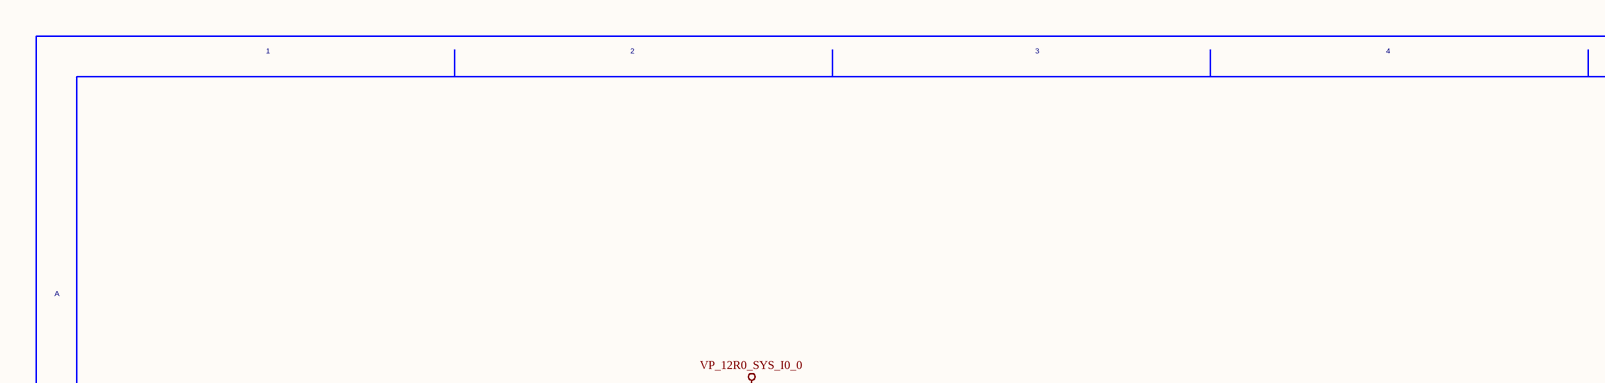
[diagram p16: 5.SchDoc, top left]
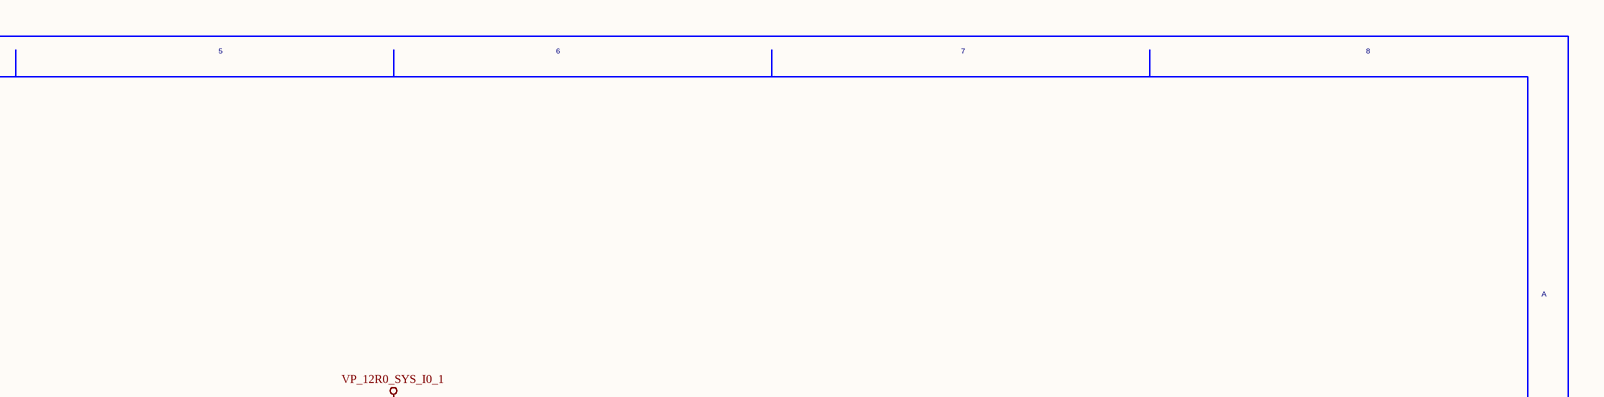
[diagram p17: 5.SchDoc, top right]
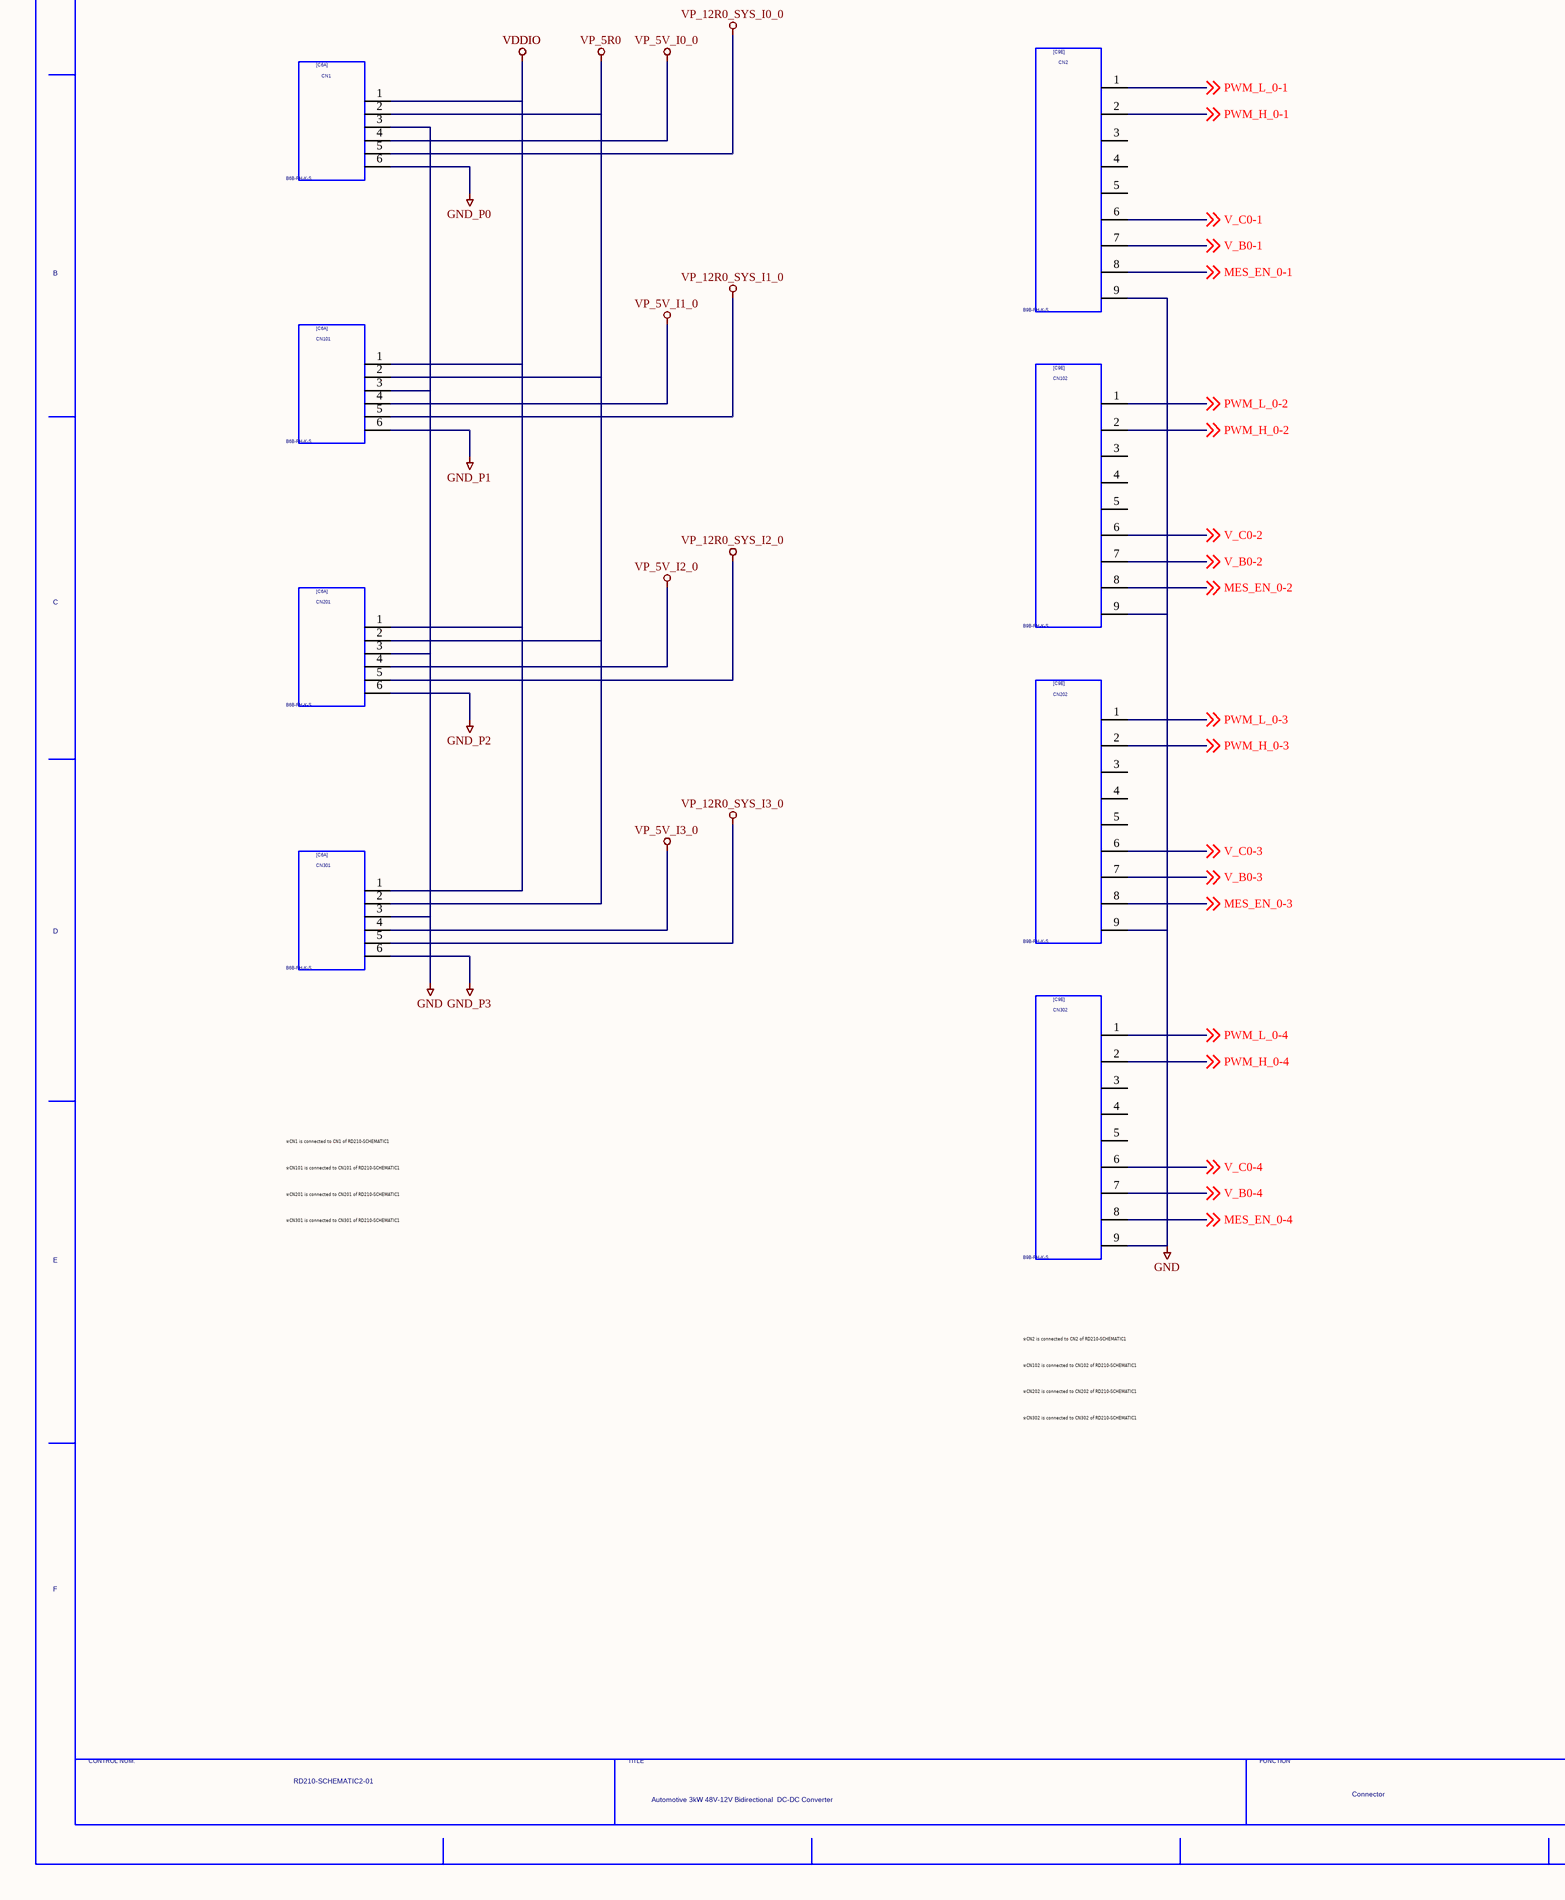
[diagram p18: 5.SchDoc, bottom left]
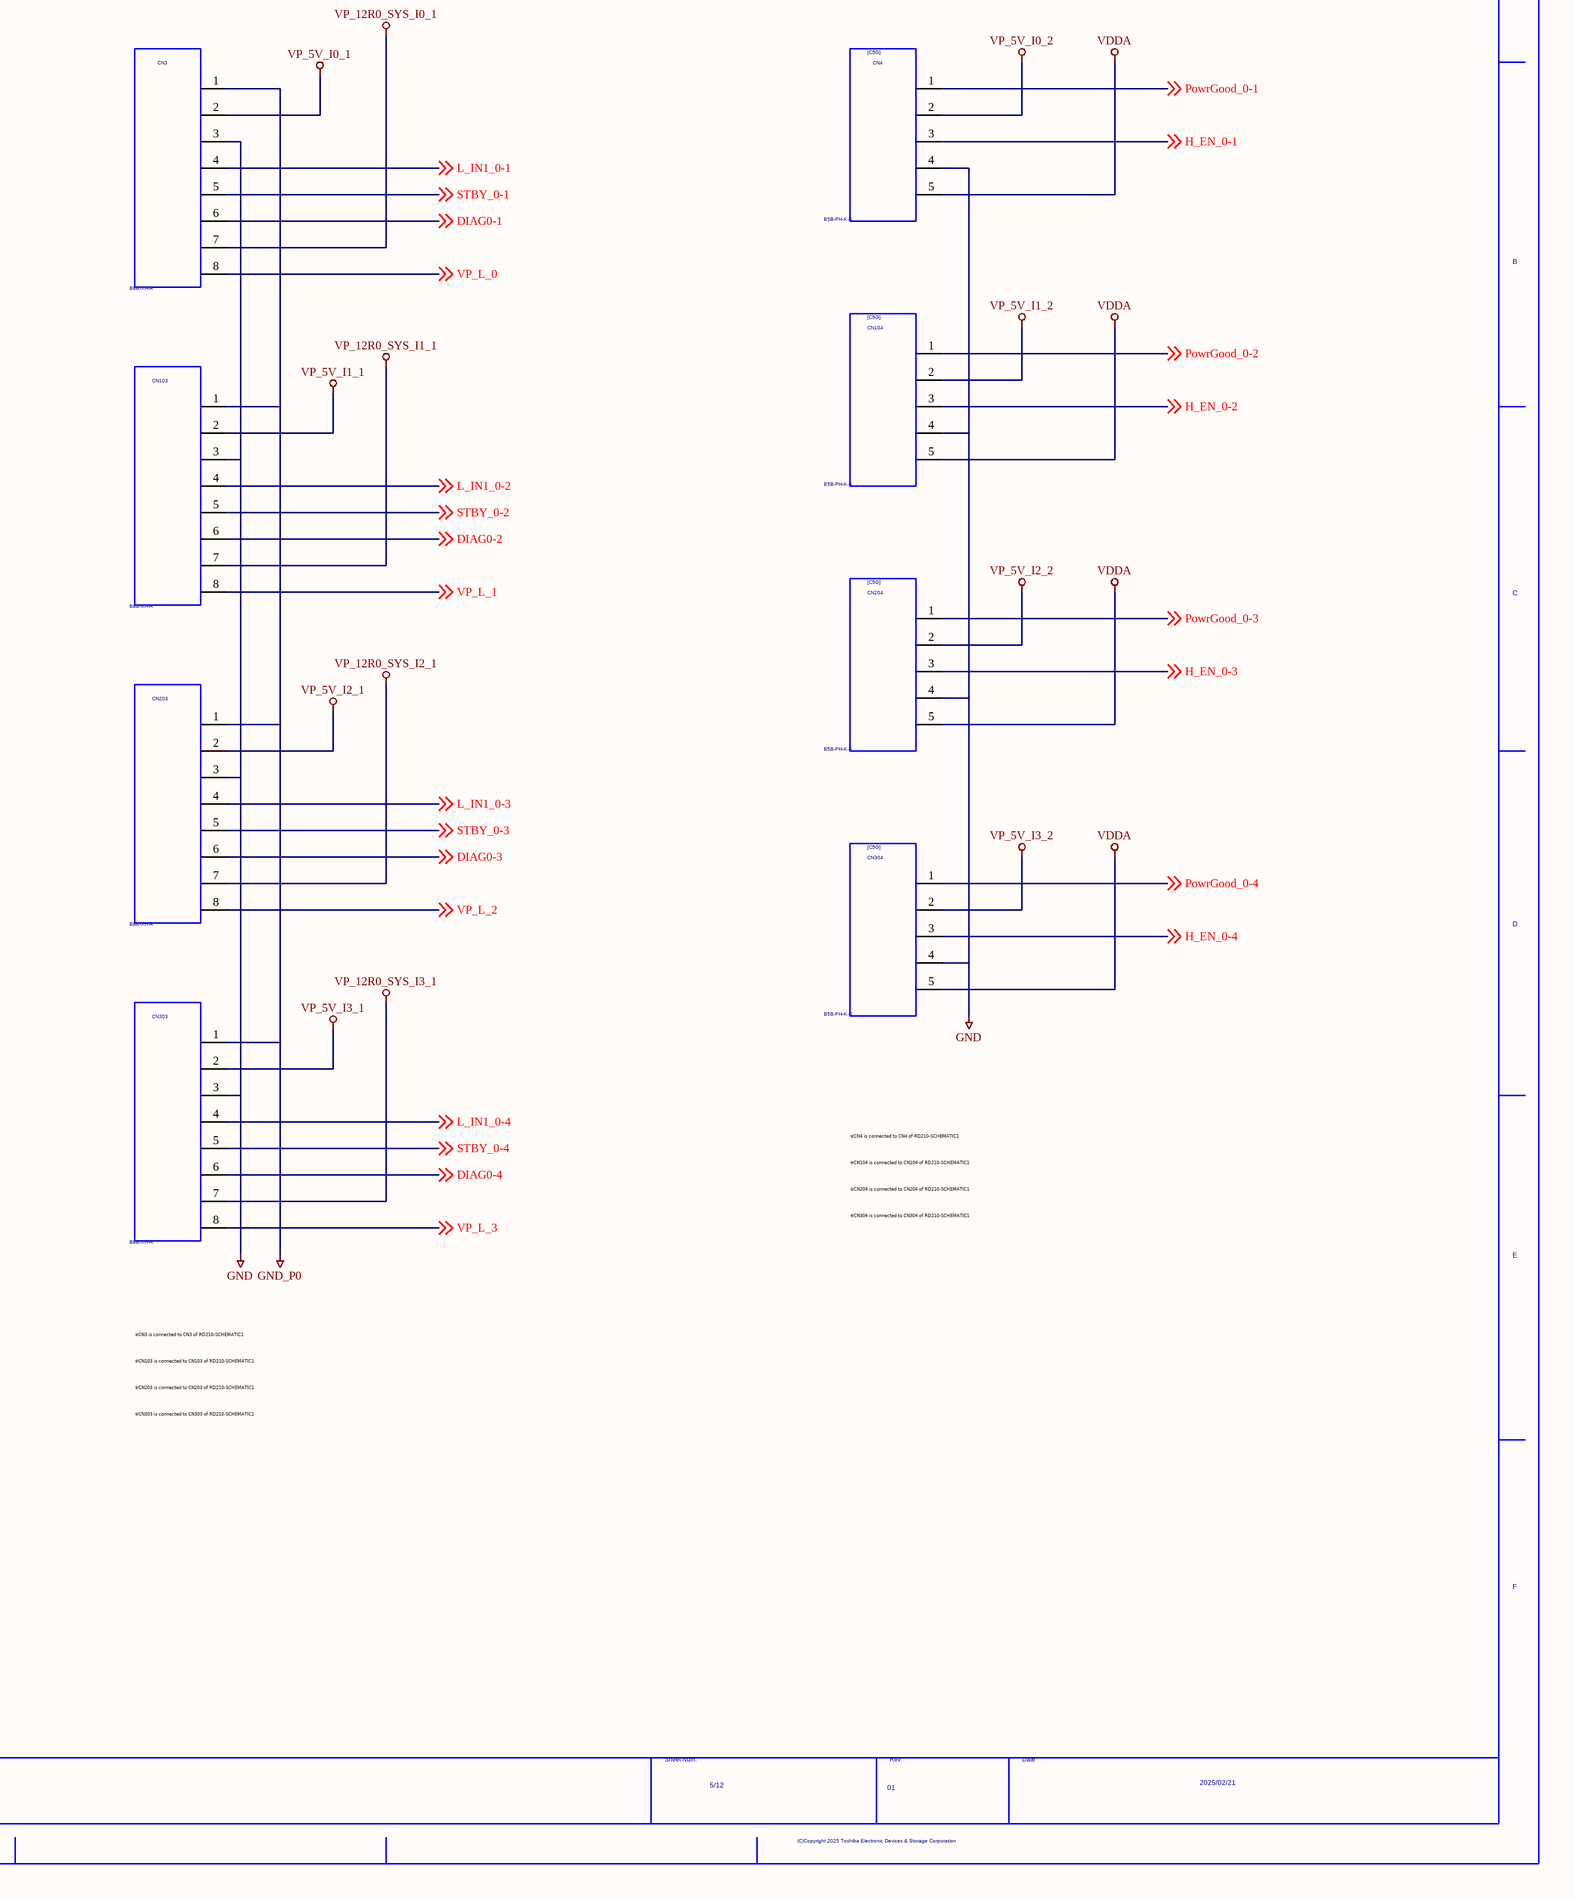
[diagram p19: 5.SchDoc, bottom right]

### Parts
(Parts that share a designator on the sheet are numbered #1, #2 ... from top to bottom, then left to right.)
CN1  VAL3: B6B-PH-K-S  (hidden comment: C6A)
CN2  VAL3: B9B-PH-K-S  (hidden comment: C9E)
CN3  B8B-XH-A
CN4  VAL3: B5B-PH-K-S  (hidden comment: C5G)
CN101  VAL3: B6B-PH-K-S  (hidden comment: C6A)
CN102  VAL3: B9B-PH-K-S  (hidden comment: C9E)
CN103  B8B-XH-A
CN104  VAL3: B5B-PH-K-S  (hidden comment: C5G)
CN201  VAL3: B6B-PH-K-S  (hidden comment: C6A)
CN202  VAL3: B9B-PH-K-S  (hidden comment: C9E)
CN203  B8B-XH-A
CN204  VAL3: B5B-PH-K-S  (hidden comment: C5G)
CN301  VAL3: B6B-PH-K-S  (hidden comment: C6A)
CN302  VAL3: B9B-PH-K-S  (hidden comment: C9E)
CN303  B8B-XH-A
CN304  VAL3: B5B-PH-K-S  (hidden comment: C5G)
U?#5  DATE: 2025/02/21  DRAWINGNUMBER: RD210-SCHEMATIC2-01  TITLE: Automotive 3kW 48V-12V Bidirectional / DC-DC Converter  FUNCTION: Connector  SHEETNUMBER: 5/12  REVISION: 01  (hidden comment: WAKU_DEF_A3)

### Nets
GND: CN1.3 CN2.9 CN3.3 CN4.4 CN101.3 CN102.9 CN103.3 CN104.4 CN201.3 CN202.9 CN203.3 CN204.4 CN301.3 CN302.9 CN303.3 CN304.4
GND_P0: CN1.6 CN3.1 CN103.1 CN203.1 CN303.1
GND_P1: CN101.6
GND_P2: CN201.6
GND_P3: CN301.6
VDDA: CN4.5 CN104.5 CN204.5 CN304.5
VDDIO: CN1.1 CN101.1 CN201.1 CN301.1
VP_5R0: CN1.2 CN101.2 CN201.2 CN301.2
VP_5V_I0_0: CN1.4
VP_5V_I0_1: CN3.2
VP_5V_I0_2: CN4.2
VP_5V_I1_0: CN101.4
VP_5V_I1_1: CN103.2
VP_5V_I1_2: CN104.2
VP_5V_I2_0: CN201.4
VP_5V_I2_1: CN203.2
VP_5V_I2_2: CN204.2
VP_5V_I3_0: CN301.4
VP_5V_I3_1: CN303.2
VP_5V_I3_2: CN304.2
VP_12R0_SYS_I0_0: CN1.5
VP_12R0_SYS_I0_1: CN3.7
VP_12R0_SYS_I1_0: CN101.5
VP_12R0_SYS_I1_1: CN103.7
VP_12R0_SYS_I2_0: CN201.5
VP_12R0_SYS_I2_1: CN203.7
VP_12R0_SYS_I3_0: CN301.5
VP_12R0_SYS_I3_1: CN303.7
DIAG0-1: CN3.6 ; off-sheet DIAG0-1
DIAG0-2: CN103.6 ; off-sheet DIAG0-2
DIAG0-3: CN203.6 ; off-sheet DIAG0-3
DIAG0-4: CN303.6 ; off-sheet DIAG0-4
H_EN_0-1: CN4.3 ; off-sheet H_EN_0-1
H_EN_0-2: CN104.3 ; off-sheet H_EN_0-2
H_EN_0-3: CN204.3 ; off-sheet H_EN_0-3
H_EN_0-4: CN304.3 ; off-sheet H_EN_0-4
L_IN1_0-1: CN3.4 ; off-sheet L_IN1_0-1
L_IN1_0-2: CN103.4 ; off-sheet L_IN1_0-2
L_IN1_0-3: CN203.4 ; off-sheet L_IN1_0-3
L_IN1_0-4: CN303.4 ; off-sheet L_IN1_0-4
MES_EN_0-1: CN2.8 ; off-sheet MES_EN_0-1
MES_EN_0-2: CN102.8 ; off-sheet MES_EN_0-2
MES_EN_0-3: CN202.8 ; off-sheet MES_EN_0-3
MES_EN_0-4: CN302.8 ; off-sheet MES_EN_0-4
PowrGood_0-1: CN4.1 ; off-sheet PowrGood_0-1
PowrGood_0-2: CN104.1 ; off-sheet PowrGood_0-2
PowrGood_0-3: CN204.1 ; off-sheet PowrGood_0-3
PowrGood_0-4: CN304.1 ; off-sheet PowrGood_0-4
PWM_H_0-1: CN2.2 ; off-sheet PWM_H_0-1
PWM_H_0-2: CN102.2 ; off-sheet PWM_H_0-2
PWM_H_0-3: CN202.2 ; off-sheet PWM_H_0-3
PWM_H_0-4: CN302.2 ; off-sheet PWM_H_0-4
PWM_L_0-1: CN2.1 ; off-sheet PWM_L_0-1
PWM_L_0-2: CN102.1 ; off-sheet PWM_L_0-2
PWM_L_0-3: CN202.1 ; off-sheet PWM_L_0-3
PWM_L_0-4: CN302.1 ; off-sheet PWM_L_0-4
STBY_0-1: CN3.5 ; off-sheet STBY_0-1
STBY_0-2: CN103.5 ; off-sheet STBY_0-2
STBY_0-3: CN203.5 ; off-sheet STBY_0-3
STBY_0-4: CN303.5 ; off-sheet STBY_0-4
V_B0-1: CN2.7 ; off-sheet V_B0-1
V_B0-2: CN102.7 ; off-sheet V_B0-2
V_B0-3: CN202.7 ; off-sheet V_B0-3
V_B0-4: CN302.7 ; off-sheet V_B0-4
V_C0-1: CN2.6 ; off-sheet V_C0-1
V_C0-2: CN102.6 ; off-sheet V_C0-2
V_C0-3: CN202.6 ; off-sheet V_C0-3
V_C0-4: CN302.6 ; off-sheet V_C0-4
VP_L_0: CN3.8 ; off-sheet VP_L_0
VP_L_1: CN103.8 ; off-sheet VP_L_1
VP_L_2: CN203.8 ; off-sheet VP_L_2
VP_L_3: CN303.8 ; off-sheet VP_L_3

Not connected (* = marked no-connect by the designer): CN2 3 4 5; CN102 3 4 5; CN202 3 4 5; CN302 3 4 5

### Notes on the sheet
- ※CN1 is connected to CN1 of RD210-SCHEMATIC1
- ※CN101 is connected to CN101 of RD210-SCHEMATIC1
- ※CN104 is connected to CN104 of RD210-SCHEMATIC1
- ※CN4 is connected to CN4 of RD210-SCHEMATIC1
- ※CN201 is connected to CN201 of RD210-SCHEMATIC1
- ※CN301 is connected to CN301 of RD210-SCHEMATIC1
- ※CN204 is connected to CN204 of RD210-SCHEMATIC1
- ※CN304 is connected to CN304 of RD210-SCHEMATIC1
- ※CN2 is connected to CN2 of RD210-SCHEMATIC1
- ※CN102 is connected to CN102 of RD210-SCHEMATIC1
- ※CN3 is connected to CN3 of RD210-SCHEMATIC1
- ※CN103 is connected to CN103 of RD210-SCHEMATIC1
- ※CN202 is connected to CN202 of RD210-SCHEMATIC1
- ※CN302 is connected to CN302 of RD210-SCHEMATIC1
- ※CN203 is connected to CN203 of RD210-SCHEMATIC1
- ※CN303 is connected to CN303 of RD210-SCHEMATIC1

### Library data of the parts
CN1 CN101 CN201 CN301 = C6A: SAVEAREA0: -13050,-324,32905,28692; SAVECOUNT: 22; TIME: 13:28:28; UPDATEUSER: tomizawa-y; UPDATETIME: 10:39:55; OriginalSymbolOrigin: (2540,25400); CDBNAME: CN
CN2 CN102 CN202 CN302 = C9E: SAVEAREA0: -48823,-644,68147,57583; TIME: 12:01:18; UPDATEUSER: 19990028; UPDATETIME: 10:28:58; SAVECOUNT: 6; OriginalSymbolOrigin: (2540,53340); CDBNAME: CN
CN3 CN103 CN203 CN303 = B8B-XH-A: MANUFACTURER: AVX; ITEM: CAP Ceramic; VAL2: 100V; SIZECODESMD: 1608; VALUE4: NP0; VAL1: 150p; TIME: 08:44:46; UPDATEUSER: sptcae13; UPDATETIME: 13:09:45; SAVECOUNT: 4; SAVEAREA0: -63668,-57919,68911,14627; OriginalSymbolOrigin: (0,0); CDBNAME: CN
CN4 CN104 CN204 CN304 = C5G: SAVEAREA0: -54324,-10433,76651,49246; TIME: 08:44:29; UPDATEUSER: w90028dm; UPDATETIME: 15:50:21; SAVECOUNT: 7; OriginalSymbolOrigin: (5080,35560); CDBNAME: CN
U?#5 = WAKU_DEF_A3: PLOTTIME: HH:MM; SAVEAREA0: -45080,-4508,463680,304612; TIME: 09:45:21; UPDATEUSER: t5459927; UPDATETIME: 09:54:21; SAVECOUNT: 19; ZONEOFFSETX: 36; ZONEOFFSETY: -24; OriginalSymbolOrigin: (12700,-12700); SHTSAVECOUNT: 33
